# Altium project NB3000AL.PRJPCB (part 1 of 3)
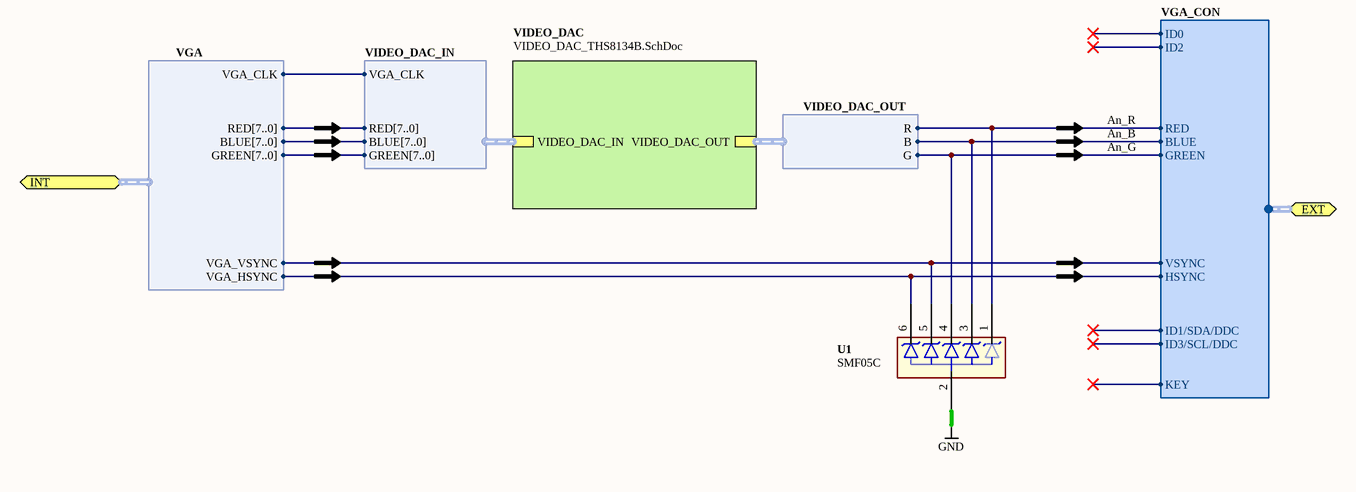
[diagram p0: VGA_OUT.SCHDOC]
ProjectAddress1: 3 Minna Close; ProjectAddress2: Belrose; ProjectAddress3: NSW 2085; ProjectAddress4: Australia; ProjectAssyNum: D-820-0053; ProjectOrganization: Altium Limited; ProjectRevision: 01; ProjectTitle: NB3000AL - Altera; ProjectTotalSheets: 106
22 sheets, 385 parts. Net scope: hierarchical (ports join the sheet entries above them; power ports are global).
Board files: NB3000AL.PcbDoc, NB3000AL_Panel.PcbDoc
Sheets:
  VGA_OUT.SCHDOC
    VIDEO_DAC = VIDEO_DAC_THS8134B.SchDoc
  Audio_Codec.SchDoc
  PSU.SchDoc
  FPGA.SCHDOC
    USER_DECOUPLING_CAPS_1V2 = FPGA_Bypass_1V2.SCHDOC
    USER_DECOUPLING_CAPS_3V3 = FPGA_Bypass_3V3.SCHDOC
    U_FPGA_Power = FPGA_NonIO.SchDoc
    PULLDOWN = PULLDNx3.SCHDOC
    PULLDOWN = PULLDNx3.SCHDOC
    PULLDOWN = PULLDNx3.SCHDOC
    PULLDOWN = PULLDNx3.SCHDOC
    PULLDOWN = PULLDNx3.SCHDOC
    PULLDOWN = PULLDNx3.SCHDOC
    PULLDOWN = PULLDNx3.SCHDOC
    PULLDOWN = PULLDNx3.SCHDOC
  LED_RGB_SMDx8.SCHDOC
  PWJACK+SWITCH.SchDoc
  Ethernet_RTL8201CL.SchDoc
  HOST_JTAG.SchDoc
  USERPWR.SchDoc
  Host_FPGA.SchDoc
    HOST_NonIO = HOST_FPGA_NonIO.SchDoc
    HOST_DECOUPLING_CAPS_1V2 = FPGA_Bypass_1V2.SCHDOC
    HOST_DECOUPLING_CAPS_3V3 = FPGA_Bypass_3V3.SCHDOC
    PULLDOWN = PULLDNx3.SCHDOC
    PULLDOWN = PULLDNx3.SCHDOC
  TSC_XPT2046.SchDoc
  USB_CY7C68001-56LFC.SchDoc
  OSC_24MHZ.SchDoc
  CON_AUDIO_AC99_NOMIC.SchDoc
  CON_FFC40_LCDTFT.SCHDOC
  Mounts.SchDoc

## Sheet VGA_OUT.SCHDOC: VGA Ouput
size A4; DocumentNumber: 2; PageSetup: Record=PageOptions|CenterHorizontal=True|CenterVertical=True|PrintScale=0.97|XCorrection=1.00|YCorrection=1.00|PrintKind=1|BorderSize=5000000|LeftOffset=0|BottomOffset=0|Orientation=2|PaperLength=1000|PaperWidth=1000|Scale=100|PaperSource=7|PrintQuality=-4|MediaType=1|DitherType=10|PaperKind=A4 (210 x 297 mm)|PrintScaleMode=1

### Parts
(Parts that share a designator on the sheet are numbered #1, #2 ... from top to bottom, then left to right.)
U1#1  SMF05C  [SC70_6L]

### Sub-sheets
VIDEO_DAC = VIDEO_DAC_THS8134B.SchDoc: VIDEO_DAC_OUT (harness VIDEO_DAC_OUT), VIDEO_DAC_IN (harness VIDEO_DAC_IN)

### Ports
EXT (harness VGA_CON), INT (harness VGA)

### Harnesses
VIDEO_DAC_IN: RED[7..0], GREEN[7..0], BLUE[7..0], VGA_CLK
VIDEO_DAC_OUT: B, R, G
VGA: RED[7..0], GREEN[7..0], BLUE[7..0], VGA_CLK, VGA_VSYNC, VGA_HSYNC
VGA_CON: RED, GREEN, BLUE, VSYNC, HSYNC, KEY, ID2, ID3/SCL/DDC, ID1/SDA/DDC, ID0

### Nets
GND: U1#1.2
An_B: U1#1.3 ; sheet VIDEO_DAC/VIDEO_DAC_OUT.B, port EXT.BLUE
An_G: U1#1.4 ; sheet VIDEO_DAC/VIDEO_DAC_OUT.G, port EXT.GREEN
An_R: U1#1.1 ; sheet VIDEO_DAC/VIDEO_DAC_OUT.R, port EXT.RED
NetU1#1_5: U1#1.5 ; port INT.VGA_VSYNC, port EXT.VSYNC
NetU1#1_6: U1#1.6 ; port INT.VGA_HSYNC, port EXT.HSYNC
NetU1#2_26: sheet VIDEO_DAC/VIDEO_DAC_IN.VGA_CLK, port INT.VGA_CLK

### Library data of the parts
U1#1 = D-157-0000: TVS Diode Array  For ESD and Latch-Up Protection; Junction Capacitance: 130 pF; Peak Pulse Current: 8 A; Peak Pulse Power: 100 W; Reverse Breakdown Voltage: 6 V

## Sheet VIDEO_DAC_THS8134B.SchDoc: Video DAC
size A4; Organization: Altium Limited.; Address1: Level 3, 12a Rodborough Rd; Address2: Frenchs Forest 2086; Address3: NSW; Address4: AUSTRALIA; DocumentNumber: 62; SheetNumber: 63; SheetTotal: 78
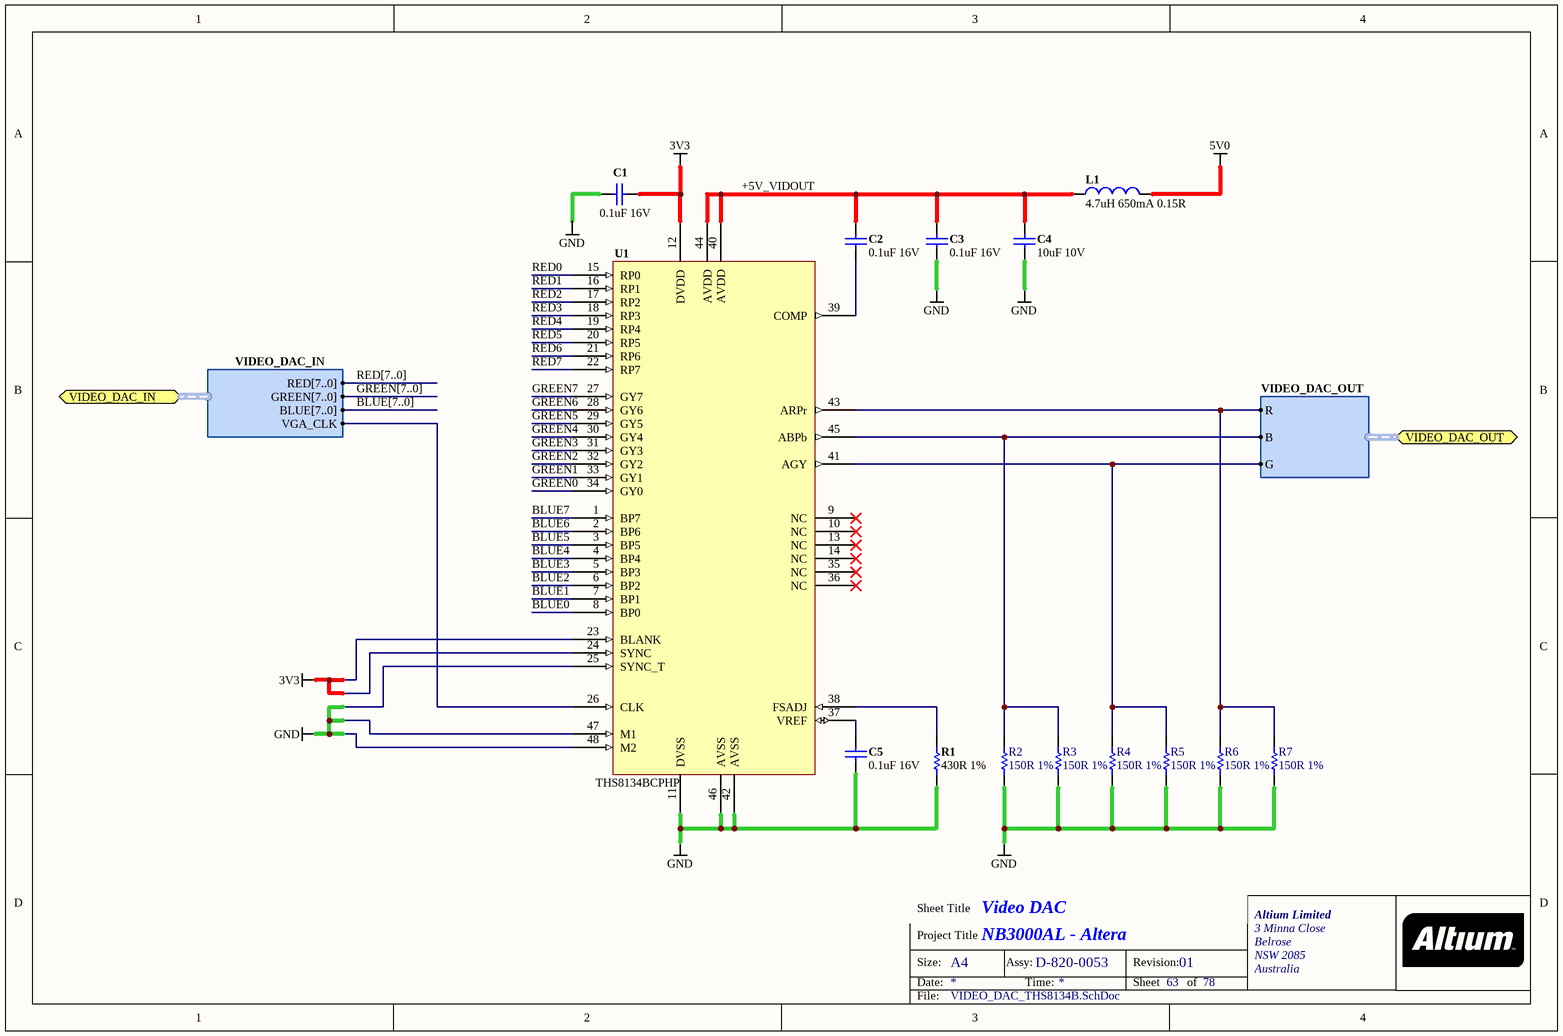
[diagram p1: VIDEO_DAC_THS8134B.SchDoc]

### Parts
(Parts that share a designator on the sheet are numbered #1, #2 ... from top to bottom, then left to right.)
C1#1  0.1uF 16V  [CAPC1005-STAR]
C2#1  0.1uF 16V  [CAPC1005-STAR]
C3#1  0.1uF 16V  [CAPC1005-STAR]
C4#1  10uF 10V  [CAPC2012-STAR]
C5#1  0.1uF 16V  [CAPC1005-STAR]
L1#1  4.7uH 650mA 0.15R  [INDC3225]
R1#1  430R 1%  [RESC1005-STAR]
R2#1  150R 1%  [RESC1005-STAR]
R3#1  150R 1%  [RESC1005-STAR]
R4#1  150R 1%  [RESC1005-STAR]
R5#1  150R 1%  [RESC1005-STAR]
R6#1  150R 1%  [RESC1005-STAR]
R7#1  150R 1%  [RESC1005-STAR]
U1#2  THS8134BCPHP  [TSQFP50P900X900_HS-48]

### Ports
VIDEO_DAC_IN (harness VIDEO_DAC_IN), VIDEO_DAC_OUT (harness VIDEO_DAC_OUT)

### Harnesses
VIDEO_DAC_OUT: B, R, G
VIDEO_DAC_IN: RED[7..0], GREEN[7..0], BLUE[7..0], VGA_CLK

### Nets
3V3: C1#1.1 U1#2.12(DVDD) U1#2.23(BLANK) U1#2.24(SYNC)
5V0: L1#1.1
GND: C1#1.2 C3#1.2 C4#1.1 C5#1.2 R1#1.1 R2#1.2 R3#1.1 R4#1.2 R5#1.1 R6#1.1 R7#1.1 U1#2.11(DVSS) U1#2.25(SYNC_T) U1#2.42(AVSS) U1#2.46(AVSS) U1#2.47(M1) U1#2.48(M2)
+5V_VIDOUT: C2#1.1 C3#1.1 C4#1.2 L1#1.2 U1#2.40(AVDD) U1#2.44(AVDD)
An_B: R2#1.1 R3#1.2 U1#2.45(ABPb) ; port VIDEO_DAC_OUT.B
An_G: R4#1.1 R5#1.2 U1#2.41(AGY) ; port VIDEO_DAC_OUT.G
An_R: R6#1.2 R7#1.2 U1#2.43(ARPr) ; port VIDEO_DAC_OUT.R
BLUE0: U1#2.8(BP0)
BLUE1: U1#2.7(BP1)
BLUE2: U1#2.6(BP2)
BLUE3: U1#2.5(BP3)
BLUE4: U1#2.4(BP4)
BLUE5: U1#2.3(BP5)
BLUE6: U1#2.2(BP6)
BLUE7: U1#2.1(BP7)
GREEN0: U1#2.34(GY0)
GREEN1: U1#2.33(GY1)
GREEN2: U1#2.32(GY2)
GREEN3: U1#2.31(GY3)
GREEN4: U1#2.30(GY4)
GREEN5: U1#2.29(GY5)
GREEN6: U1#2.28(GY6)
GREEN7: U1#2.27(GY7)
RED0: U1#2.15(RP0)
RED1: U1#2.16(RP1)
RED2: U1#2.17(RP2)
RED3: U1#2.18(RP3)
RED4: U1#2.19(RP4)
RED5: U1#2.20(RP5)
RED6: U1#2.21(RP6)
RED7: U1#2.22(RP7)
NetC2#1_2: C2#1.2 U1#2.39(COMP)
NetC5#1_1: C5#1.1 U1#2.37(VREF)
NetR1#1_2: R1#1.2 U1#2.38(FSADJ)
NetU1#2_26: U1#2.26(CLK) ; port VIDEO_DAC_IN.VGA_CLK

Not connected (* = marked no-connect by the designer): U1#2 9(NC)* 10(NC)* 13(NC)* 14(NC)* 35(NC)* 36(NC)*

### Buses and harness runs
bus BLUE[7..0]
bus GREEN[7..0]
bus RED[7..0]

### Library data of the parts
C1#1 C2#1 C3#1 C5#1 = D-101-0080: Capacitor, Ceramic, 0.1uF 10% 16V 0402 (1005) X7R; Polarity: Non-Polarized
C4#1 = D-101-0087: Capacitor, Ceramic, 10uF 10% 10V 0805 (2012) X5R; Polarity: Non-Polarized
L1#1 = D-102-0005: Inductor, 4.7uH 650mA 0.15R 1210 (3225) LQH32CN4R7M11L
R1#1 = D-100-0096: Resistor, 430R 1% 0402 (1005); Power Rating: 63 mW
R2#1 R3#1 R4#1 R5#1 R6#1 R7#1 = D-100-0005: Resistor, 150R 1% 0402 (1005); Power Rating: 63mW
U1#2 = D-222-0000: THS8134BCPHP, Triple 8-Bit, 80 MSPS Video DAC with Tri-Level Sync Generation

## Sheet Audio_Codec.SchDoc: Audio CODEC Top
size A4; DocumentNumber: 4
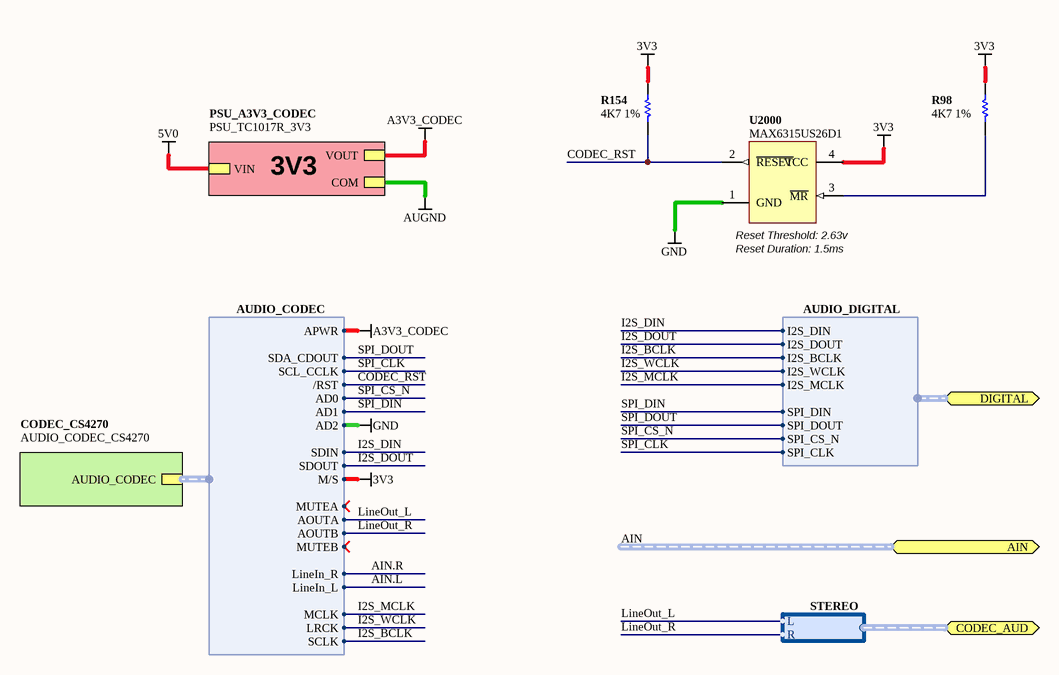
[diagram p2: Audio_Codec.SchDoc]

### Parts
(Parts that share a designator on the sheet are numbered #1, #2 ... from top to bottom, then left to right.)
R98  4K7 1%  [RESC1005-STAR]
R154#1  4K7 1%  [RESC1005-STAR]
U2000  MAX6315US26D1  [SOT143]

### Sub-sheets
CODEC_CS4270 = AUDIO_CODEC_CS4270 (file not in this document): AUDIO_CODEC (harness AUDIO_CODEC)
PSU_A3V3_CODEC = PSU_TC1017R_3V3 (file not in this document): VIN, VOUT, COM

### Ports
AIN (harness AUDIO_IN), CODEC_AUD (harness STEREO), DIGITAL (harness AUDIO_DIGITAL)

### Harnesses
AUDIO_CODEC: SDOUT, SDIN, SCLK, LRCK, MCLK, M/S, LineIn_L, LineIn_R, AOUTA, AOUTB, APWR, SCL_CCLK, AD1, SDA_CDOUT, AD0, AD2, /RST, MUTEA, MUTEB
AUDIO_DIGITAL: I2S_DOUT, I2S_DIN, I2S_BCLK, I2S_WCLK, I2S_MCLK, SPI_CLK, SPI_DIN, SPI_DOUT, SPI_CS_N
STEREO: L, R

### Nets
3V3: R98.2 R154#1.2 U2000.4(VCC) ; sheet CODEC_CS4270/AUDIO_CODEC.M/S
A3V3_CODEC: sheet PSU_A3V3_CODEC/VOUT, sheet CODEC_CS4270/AUDIO_CODEC.APWR
GND: U2000.1(GND) ; sheet CODEC_CS4270/AUDIO_CODEC.AD2
CODEC_RST: R154#1.1 U2000.2(~{RESET}) ; sheet CODEC_CS4270/AUDIO_CODEC./RST
I2S_BCLK: sheet CODEC_CS4270/AUDIO_CODEC.SCLK, port DIGITAL.I2S_BCLK
I2S_DIN: sheet CODEC_CS4270/AUDIO_CODEC.SDIN, port DIGITAL.I2S_DIN
I2S_DOUT: sheet CODEC_CS4270/AUDIO_CODEC.SDOUT, port DIGITAL.I2S_DOUT
I2S_MCLK: sheet CODEC_CS4270/AUDIO_CODEC.MCLK, port DIGITAL.I2S_MCLK
I2S_WCLK: sheet CODEC_CS4270/AUDIO_CODEC.LRCK, port DIGITAL.I2S_WCLK
LineOut_L: sheet CODEC_CS4270/AUDIO_CODEC.AOUTA, port CODEC_AUD.L
LineOut_R: sheet CODEC_CS4270/AUDIO_CODEC.AOUTB, port CODEC_AUD.R
SPI_CLK: sheet CODEC_CS4270/AUDIO_CODEC.SCL_CCLK, port DIGITAL.SPI_CLK
SPI_CS_N: sheet CODEC_CS4270/AUDIO_CODEC.AD0, port DIGITAL.SPI_CS_N
SPI_DIN: sheet CODEC_CS4270/AUDIO_CODEC.AD1, port DIGITAL.SPI_DIN
SPI_DOUT: sheet CODEC_CS4270/AUDIO_CODEC.SDA_CDOUT, port DIGITAL.SPI_DOUT
NetR98_1: R98.1 U2000.3(~{MR})

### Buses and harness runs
harness AIN = port AIN

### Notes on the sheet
- 3V3
- (near U2000) Reset Threshold: 2.63v
- (near U2000) Reset Duration: 1.5ms

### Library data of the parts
R98 R154#1 = D-100-0088: Resistor, 4K7 1% 0402 (1005); Power Rating: 63 mW; Resistance: 4.7 K
U2000 = D-243-0000: MAX6315, Open-Drain Output SOT Reset IC, Customized Reset Thresholds, Timeout Delays

## Sheet PSU.SchDoc: NB3000 POWER SUPPLIES
size A4; Organization: Altium Limited.; DocumentNumber: 7; Revision: 6
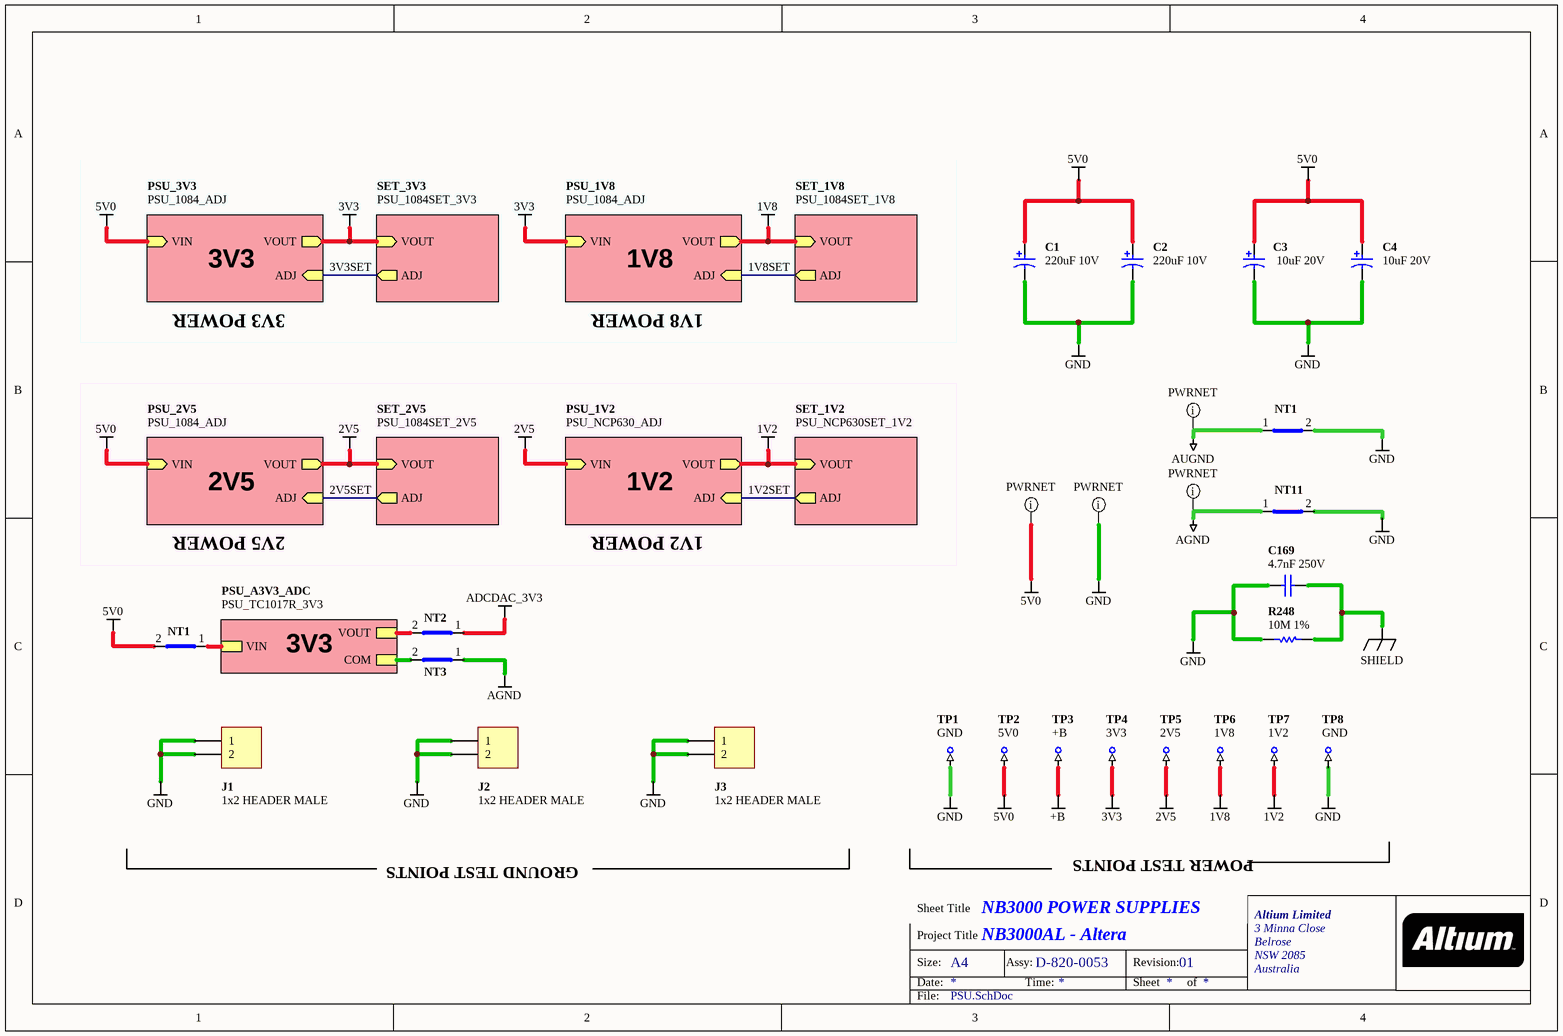
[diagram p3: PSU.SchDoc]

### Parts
(Parts that share a designator on the sheet are numbered #1, #2 ... from top to bottom, then left to right.)
C1#2  220uF 10V  [CAPC7343-STAR]
C2#2  220uF 10V  [CAPC7343-STAR]
C3#2  10uF 20V  [CAPC3528-STAR]
C4#2  10uF 20V  [CAPC3528-STAR]
C169  4.7nF 250V  [CAPM7163]
J1#1  1x2 HEADER MALE  [HDR1X2]
J2  1x2 HEADER MALE  [HDR1X2]
J3#1  1x2 HEADER MALE  [HDR1X2]
NT1#1  Net Tie SMT2  [NETTIE-SMT2-31X39]  (value not drawn)  (net tie, no BOM)
NT1#2  Net Tie SMT2  [NETTIE-SMT2-31X51]  (value not drawn)  (net tie, no BOM)
NT2#1  Net Tie SMT2  [NETTIE-SMT2-31X51]  (value not drawn)  (net tie, no BOM)
NT3#1  Net Tie SMT2  [NETTIE-SMT2-31X51]  (value not drawn)  (net tie, no BOM)
NT11#1  Net Tie SMT2  [NETTIE-SMT2-8X8]  (value not drawn)  (net tie, no BOM)
R248  10M 1%  [RESC3216]
TP1  GND  [TestPin]  (no BOM)
TP2  5V0  [TestPin]  (no BOM)
TP3  +B  [TestPin]  (no BOM)
TP4  3V3  [TestPin]  (no BOM)
TP5  2V5  [TestPin]  (no BOM)
TP6  1V8  [TestPin]  (no BOM)
TP7  1V2  [TestPin]  (no BOM)
TP8  GND  [TestPin]  (no BOM)

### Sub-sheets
PSU_1V2 = PSU_NCP630_ADJ (file not in this document): VIN (in), VOUT (out), ADJ (in)
PSU_1V8 = PSU_1084_ADJ (file not in this document): VIN (in), VOUT (out), ADJ (in)
PSU_2V5 = PSU_1084_ADJ (file not in this document): VIN (in), VOUT (out), ADJ (in)
PSU_3V3 = PSU_1084_ADJ (file not in this document): VIN (in), VOUT (out), ADJ (in)
PSU_A3V3_ADC = PSU_TC1017R_3V3 (file not in this document): VIN, VOUT, COM
SET_1V2 = PSU_NCP630SET_1V2 (file not in this document): VOUT (in), ADJ (out)
SET_1V8 = PSU_1084SET_1V8 (file not in this document): VOUT (in), ADJ (out)
SET_2V5 = PSU_1084SET_2V5 (file not in this document): VOUT (in), ADJ (out)
SET_3V3 = PSU_1084SET_3V3 (file not in this document): VOUT (in), ADJ (out)

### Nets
1V2: TP7.1 ; sheet PSU_1V2/VOUT, sheet SET_1V2/VOUT
1V8: TP6.1 ; sheet PSU_1V8/VOUT, sheet SET_1V8/VOUT
2V5: TP5.1 ; sheet PSU_1V2/VIN, sheet PSU_2V5/VOUT, sheet SET_2V5/VOUT
3V3: TP4.1 ; sheet PSU_1V8/VIN, sheet PSU_3V3/VOUT, sheet SET_3V3/VOUT
5V0: C1#2.1 C2#2.1 C3#2.1 C4#2.1 NT1#2.2(Net2) TP2.1 ; sheet PSU_2V5/VIN, sheet PSU_3V3/VIN
+B: TP3.1
ADCDAC_3V3: NT2#1.1(Net1)
AGND: NT3#1.1(Net1) NT11#1.1(Net1)
AUGND: NT1#1.1(Net1)
GND: C1#2.2 C2#2.2 C3#2.2 C4#2.2 C169.2 J1#1.1 J1#1.2 J2.1 J2.2 J3#1.1 J3#1.2 NT1#1.2(Net2) NT11#1.2(Net2) R248.2 TP1.1 TP8.1
SHIELD: C169.1 R248.1
1V2SET: sheet PSU_1V2/ADJ, sheet SET_1V2/ADJ
1V8SET: sheet PSU_1V8/ADJ, sheet SET_1V8/ADJ
2V5SET: sheet PSU_2V5/ADJ, sheet SET_2V5/ADJ
3V3SET: sheet PSU_3V3/ADJ, sheet SET_3V3/ADJ
NetNT1#2_1: NT1#2.1(Net1) ; sheet PSU_A3V3_ADC/VIN
NetNT2#1_2: NT2#1.2(Net2) ; sheet PSU_A3V3_ADC/VOUT
NetNT3#1_2: NT3#1.2(Net2) ; sheet PSU_A3V3_ADC/COM

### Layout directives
net class PWRNET: 5V0, AGND, AUGND, GND

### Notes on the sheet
- 3V3
- 3V3 POWER
- 1V8
- 1V8 POWER
- 2V5
- 1V2
- 2V5 POWER
- 1V2 POWER
- POWER TEST POINTS
- GROUND TEST POINTS

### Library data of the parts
C1#2 C2#2 = D-101-0088: Capacitor, Tantalum, 220uF 10% 10V MCCT-D (7343-31); Polarity: Polarized
C3#2 C4#2 = D-101-0007: Capacitor, Tantalum, 10uF 10% 20V MCCT-B (3528); Polarity: Polarized
C169 = D-101-0019: Capacitor, Ceramic, 4.7nF 20% 250V Panasonic BC J Lead (CAPM7163) Y5V; Polarity: Non-Polarized; Tolerance: 20% %
J1#1 J2 J3#1 = D-300-0020: Header IDC, 2 x 1 Pin Vertical 2.54mm Pitch (Non-Boxed, Male); Max Current: 3 A
NT1#1 NT11#1 = D-002-0004: Net-Tie, Surface Mount, 2 x 2.0mm x 0.8mm SMT Pads - For 0.8mm Track
NT1#2 NT2#1 NT3#1 = D-002-0003: Net-Tie, Surface Mount, 2 x 1.6mm x 0.8mm SMT Pads - For 0.8mm Track
R248 = D-100-0059: Resistor, 10M 1%1206 (3216); Power Rating: 250 mW
TP1-TP8 = D-006-0000: Test Point, PCB Mount with Silkscreen Box

## Sheet FPGA.SCHDOC: USER FPGA Connections
size A0; Organization: Altium Limited.; PageSetup: Record=PageOptions|CenterHorizontal=True|CenterVertical=True|PrintScale=0.50|XCorrection=1.00|YCorrection=1.00|PrintKind=0|BorderSize=5000000|LeftOffset=0|BottomOffset=0|Orientation=2|PaperLength=4199|PaperWidth=2969|Scale=100|PaperSource=7|PrintQuality=600|MediaType=1|DitherType=10|PaperKind=A3 (297 x 420 mm)|PrintScaleMode=1
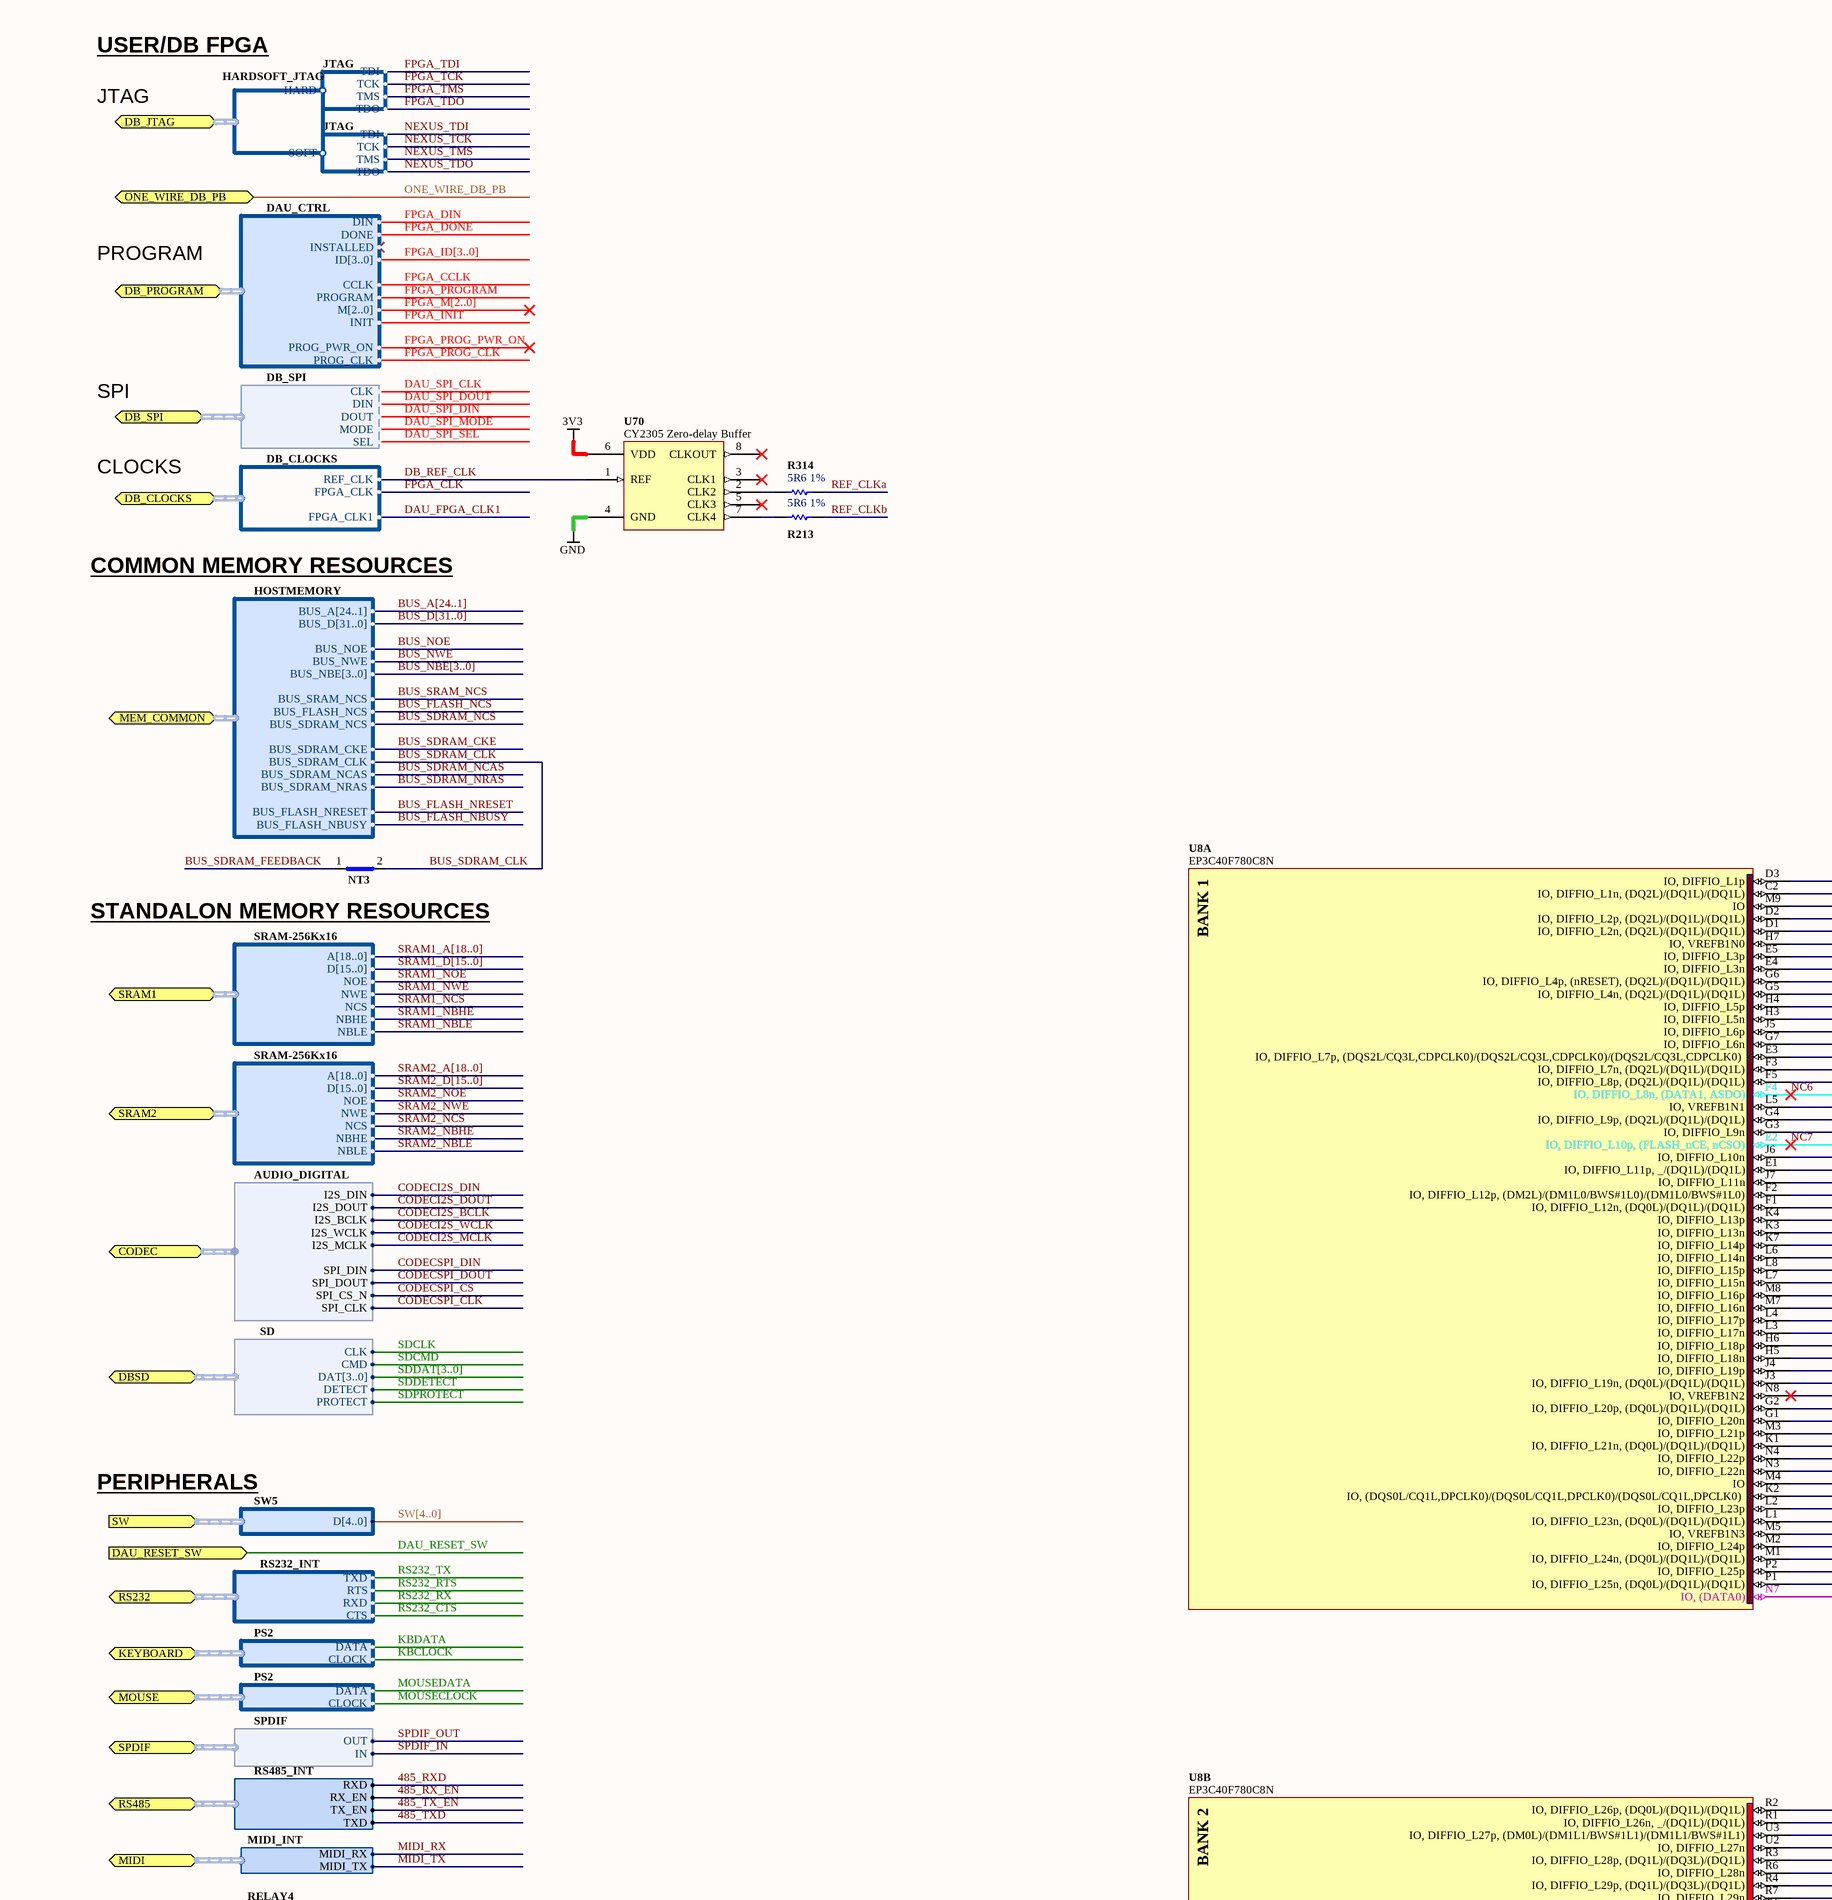
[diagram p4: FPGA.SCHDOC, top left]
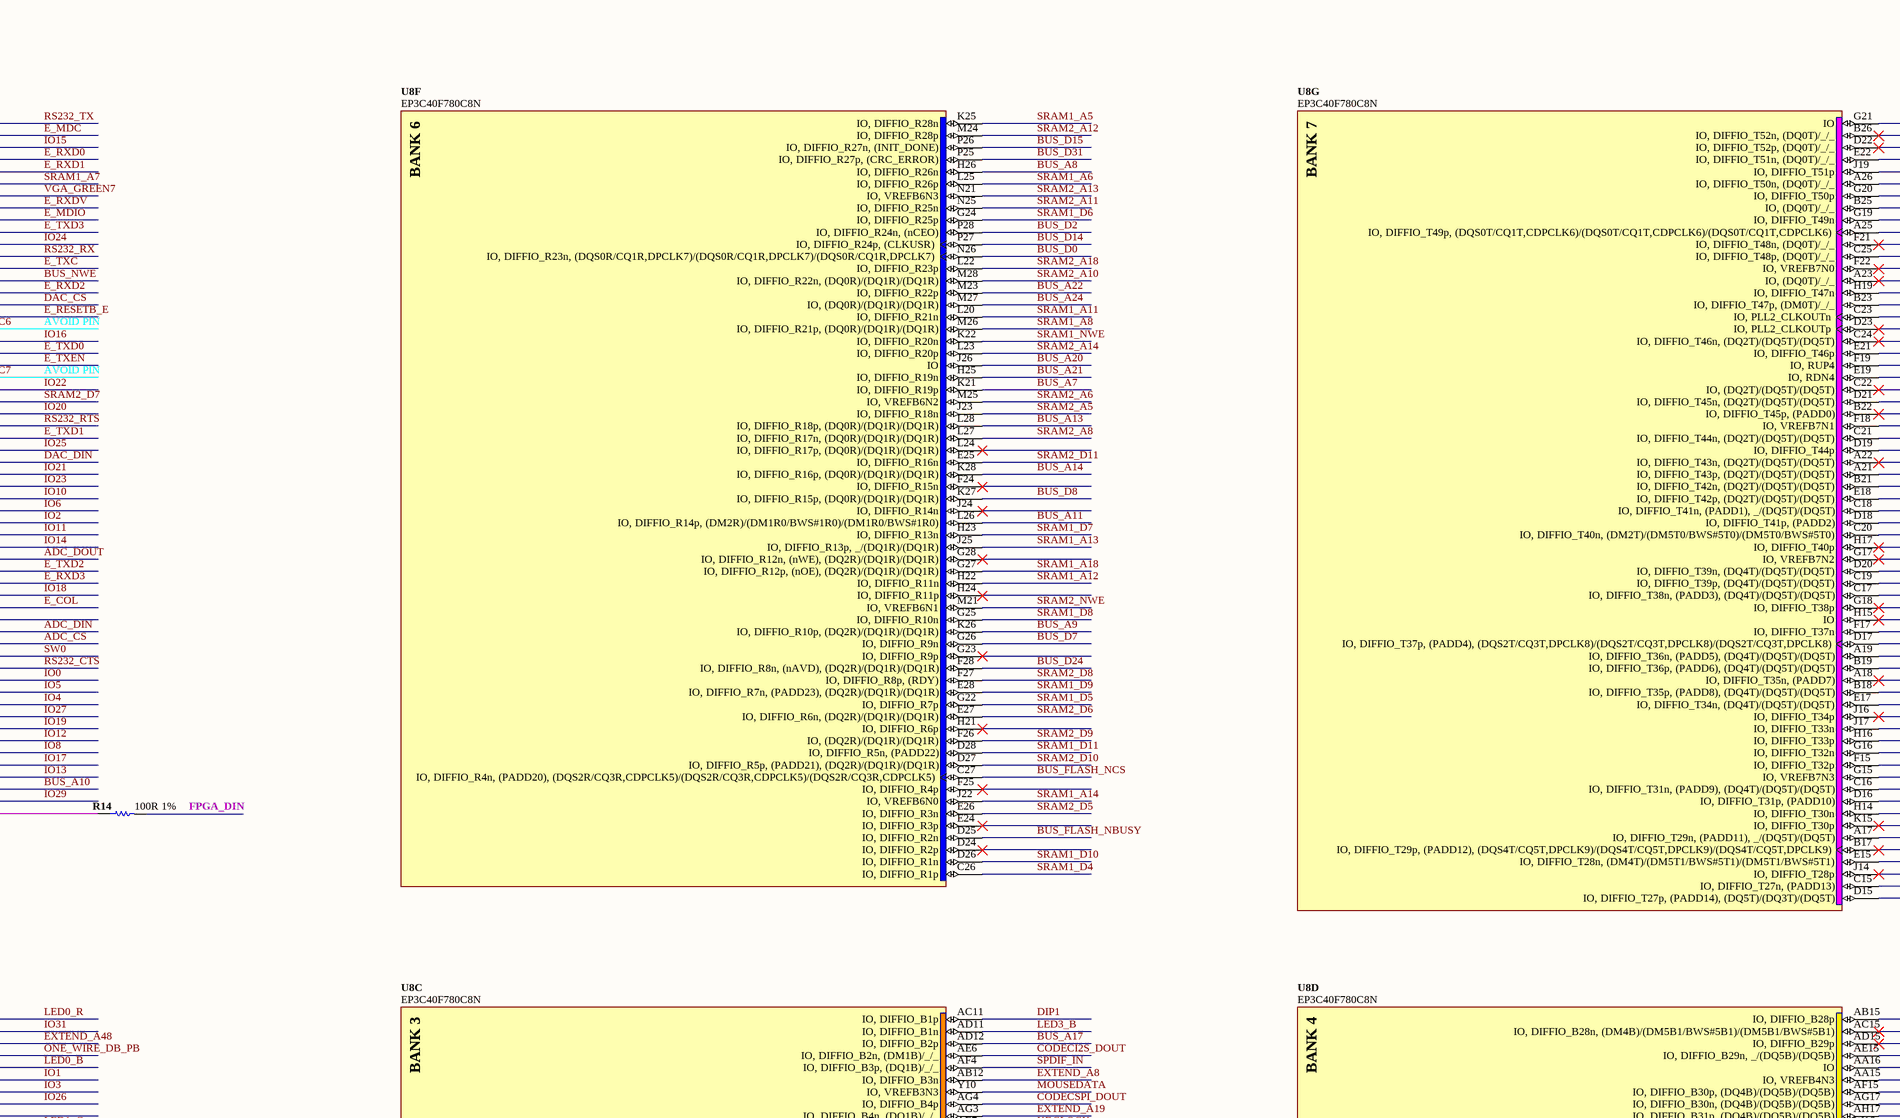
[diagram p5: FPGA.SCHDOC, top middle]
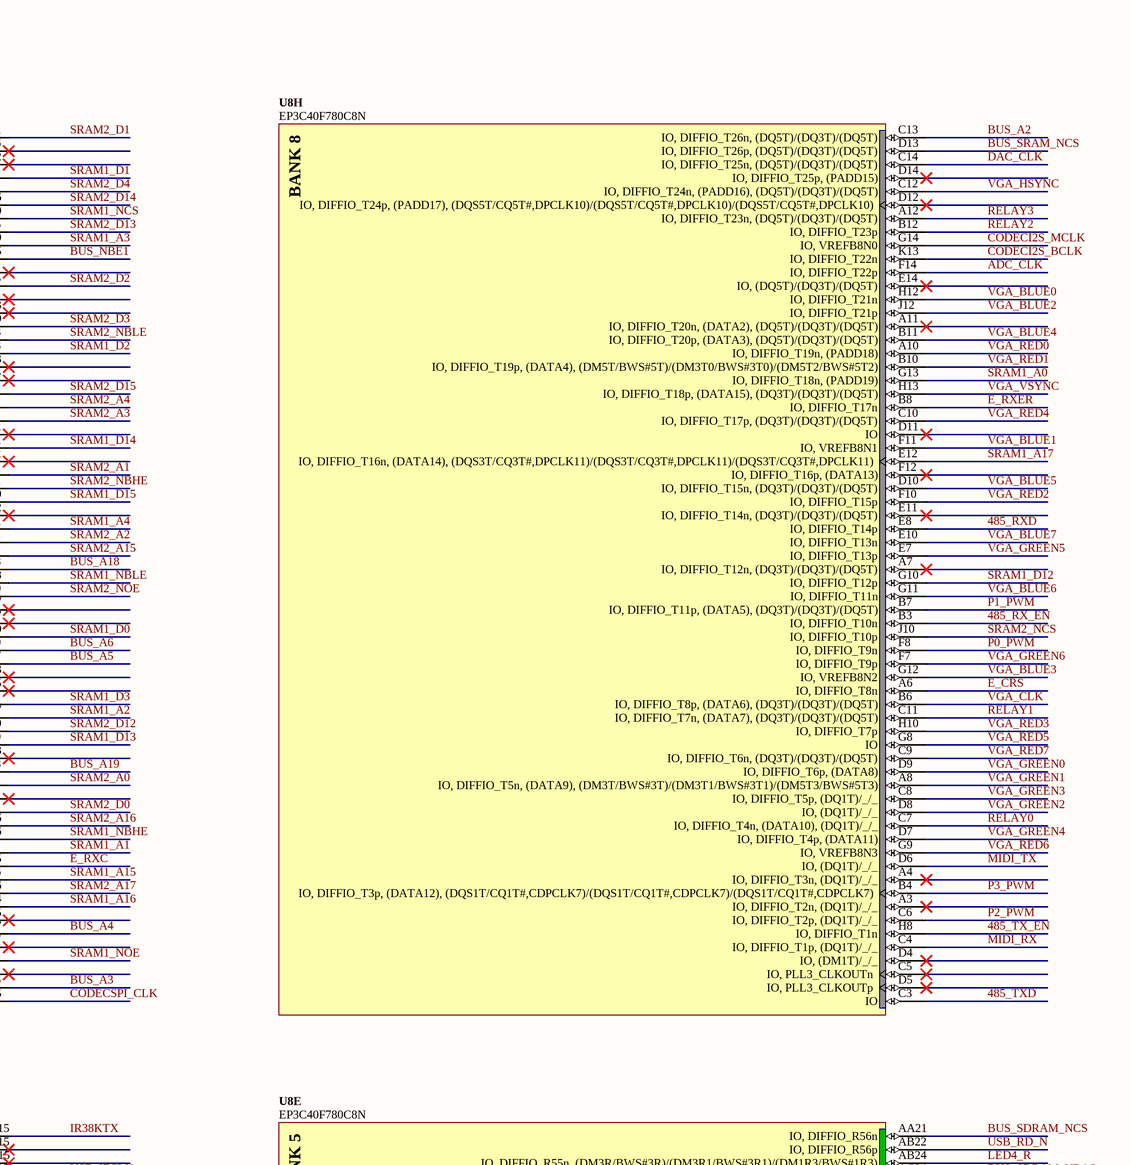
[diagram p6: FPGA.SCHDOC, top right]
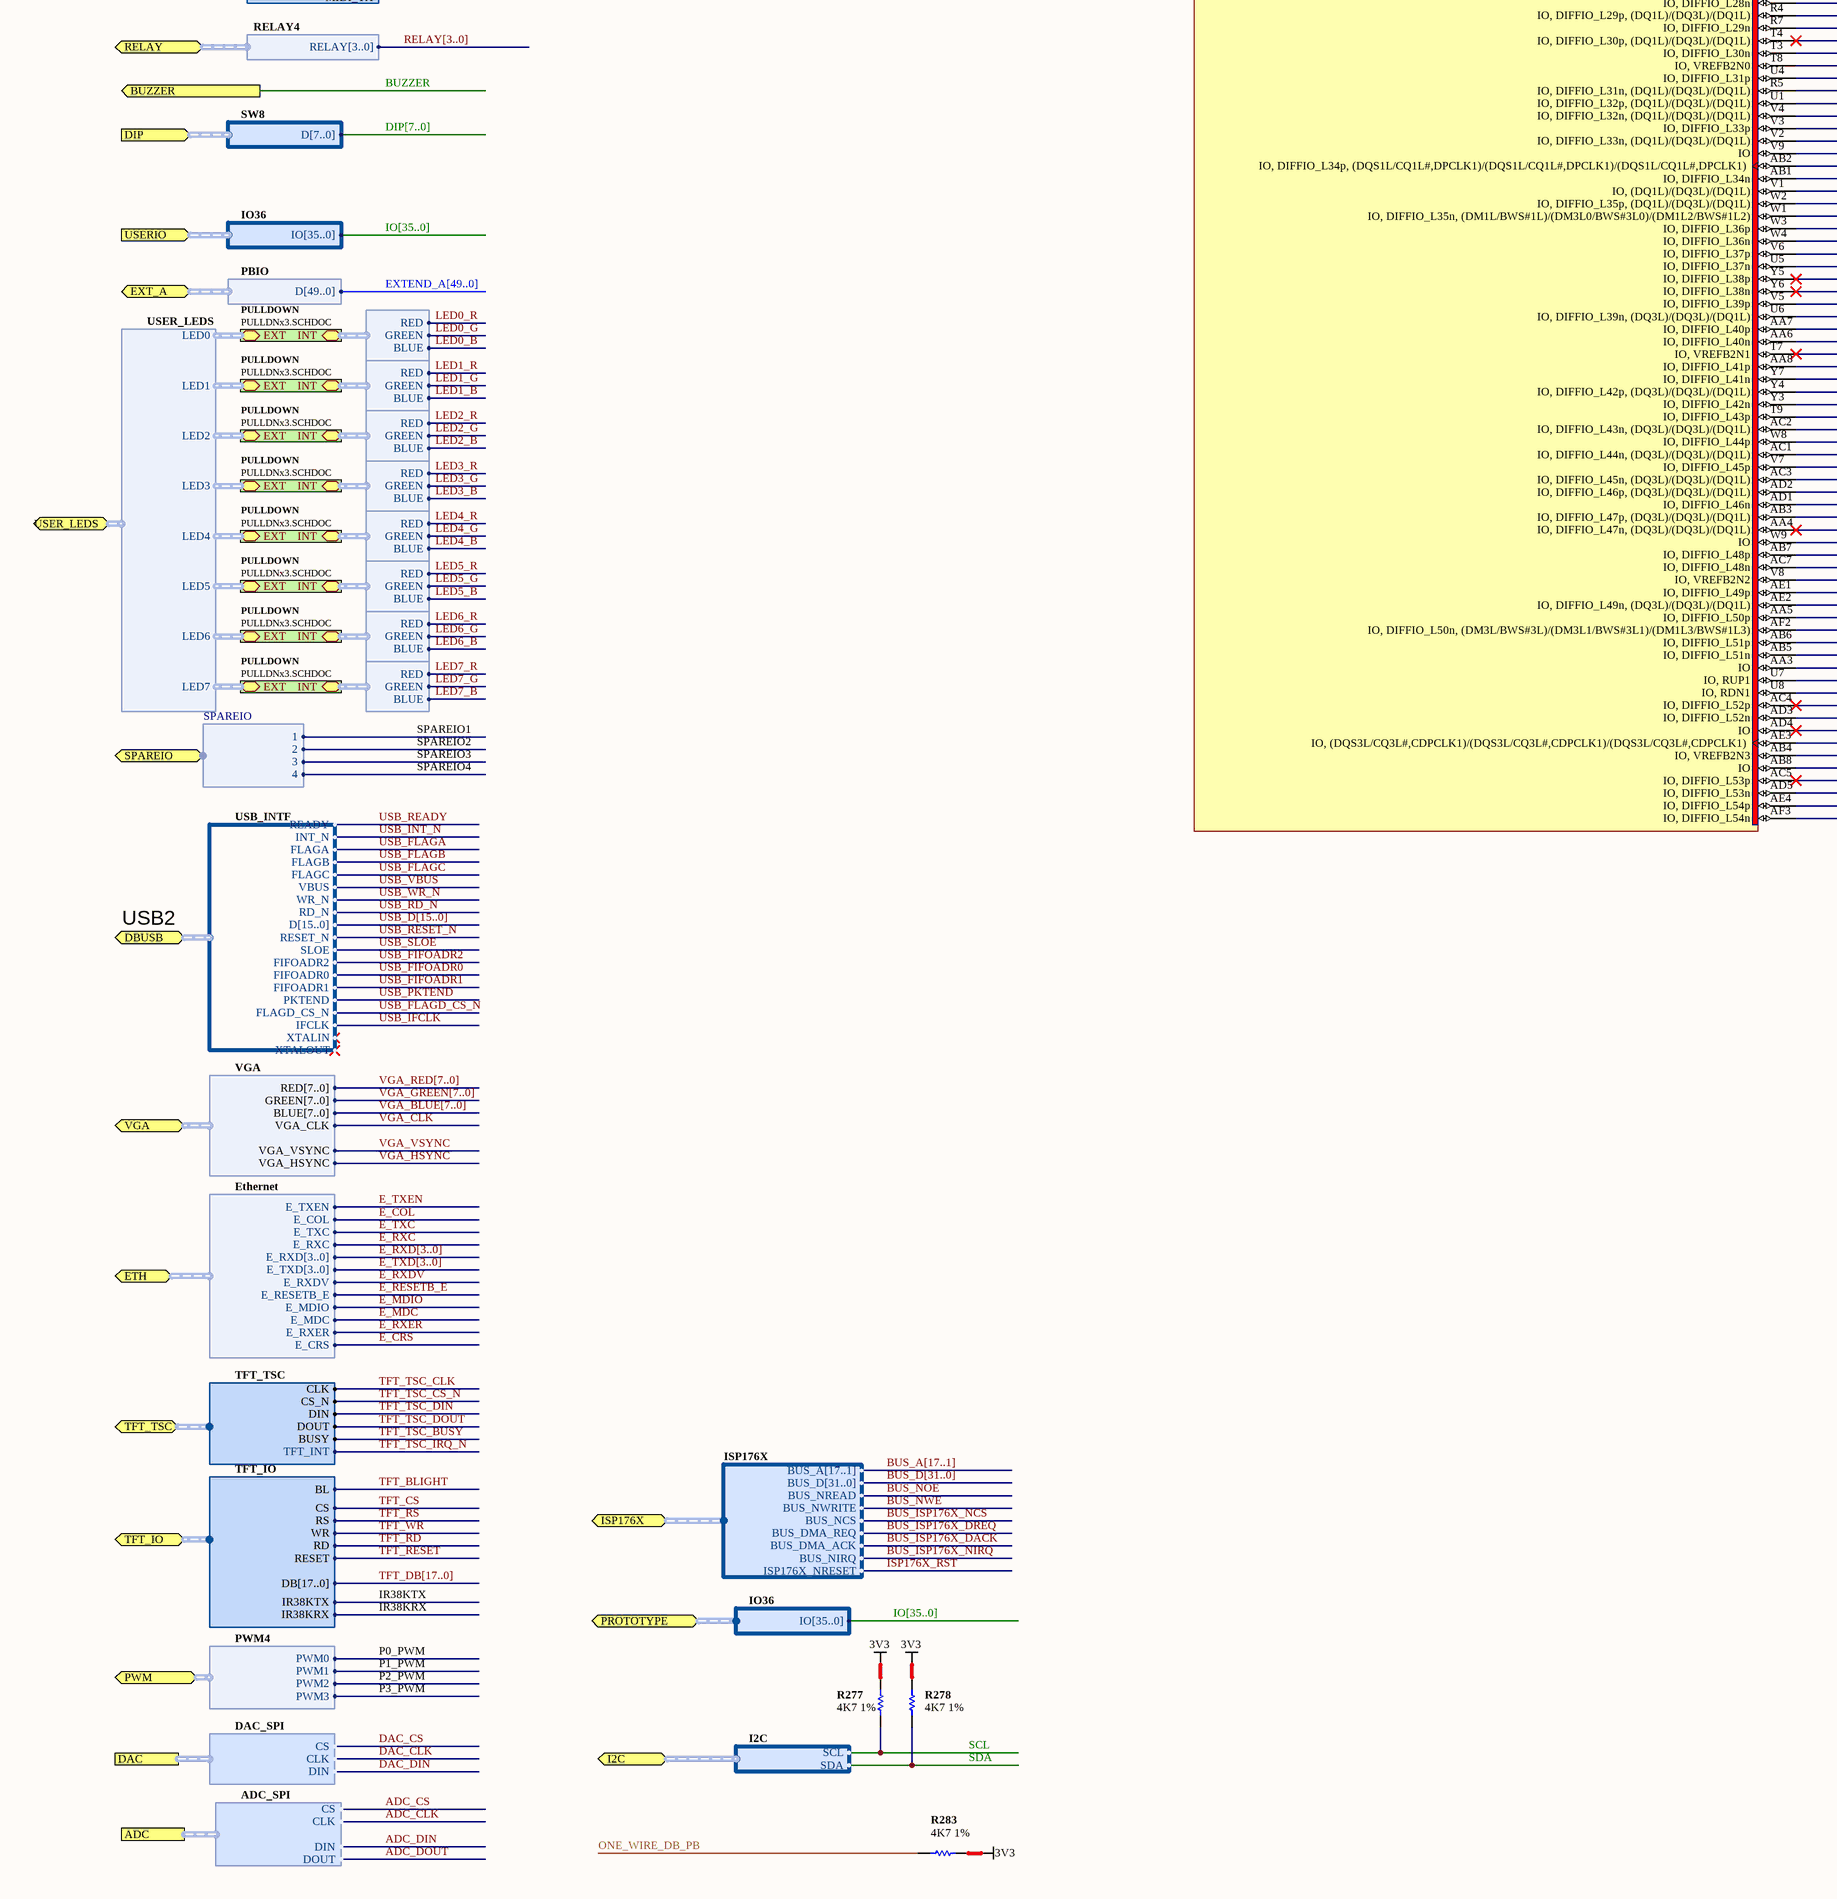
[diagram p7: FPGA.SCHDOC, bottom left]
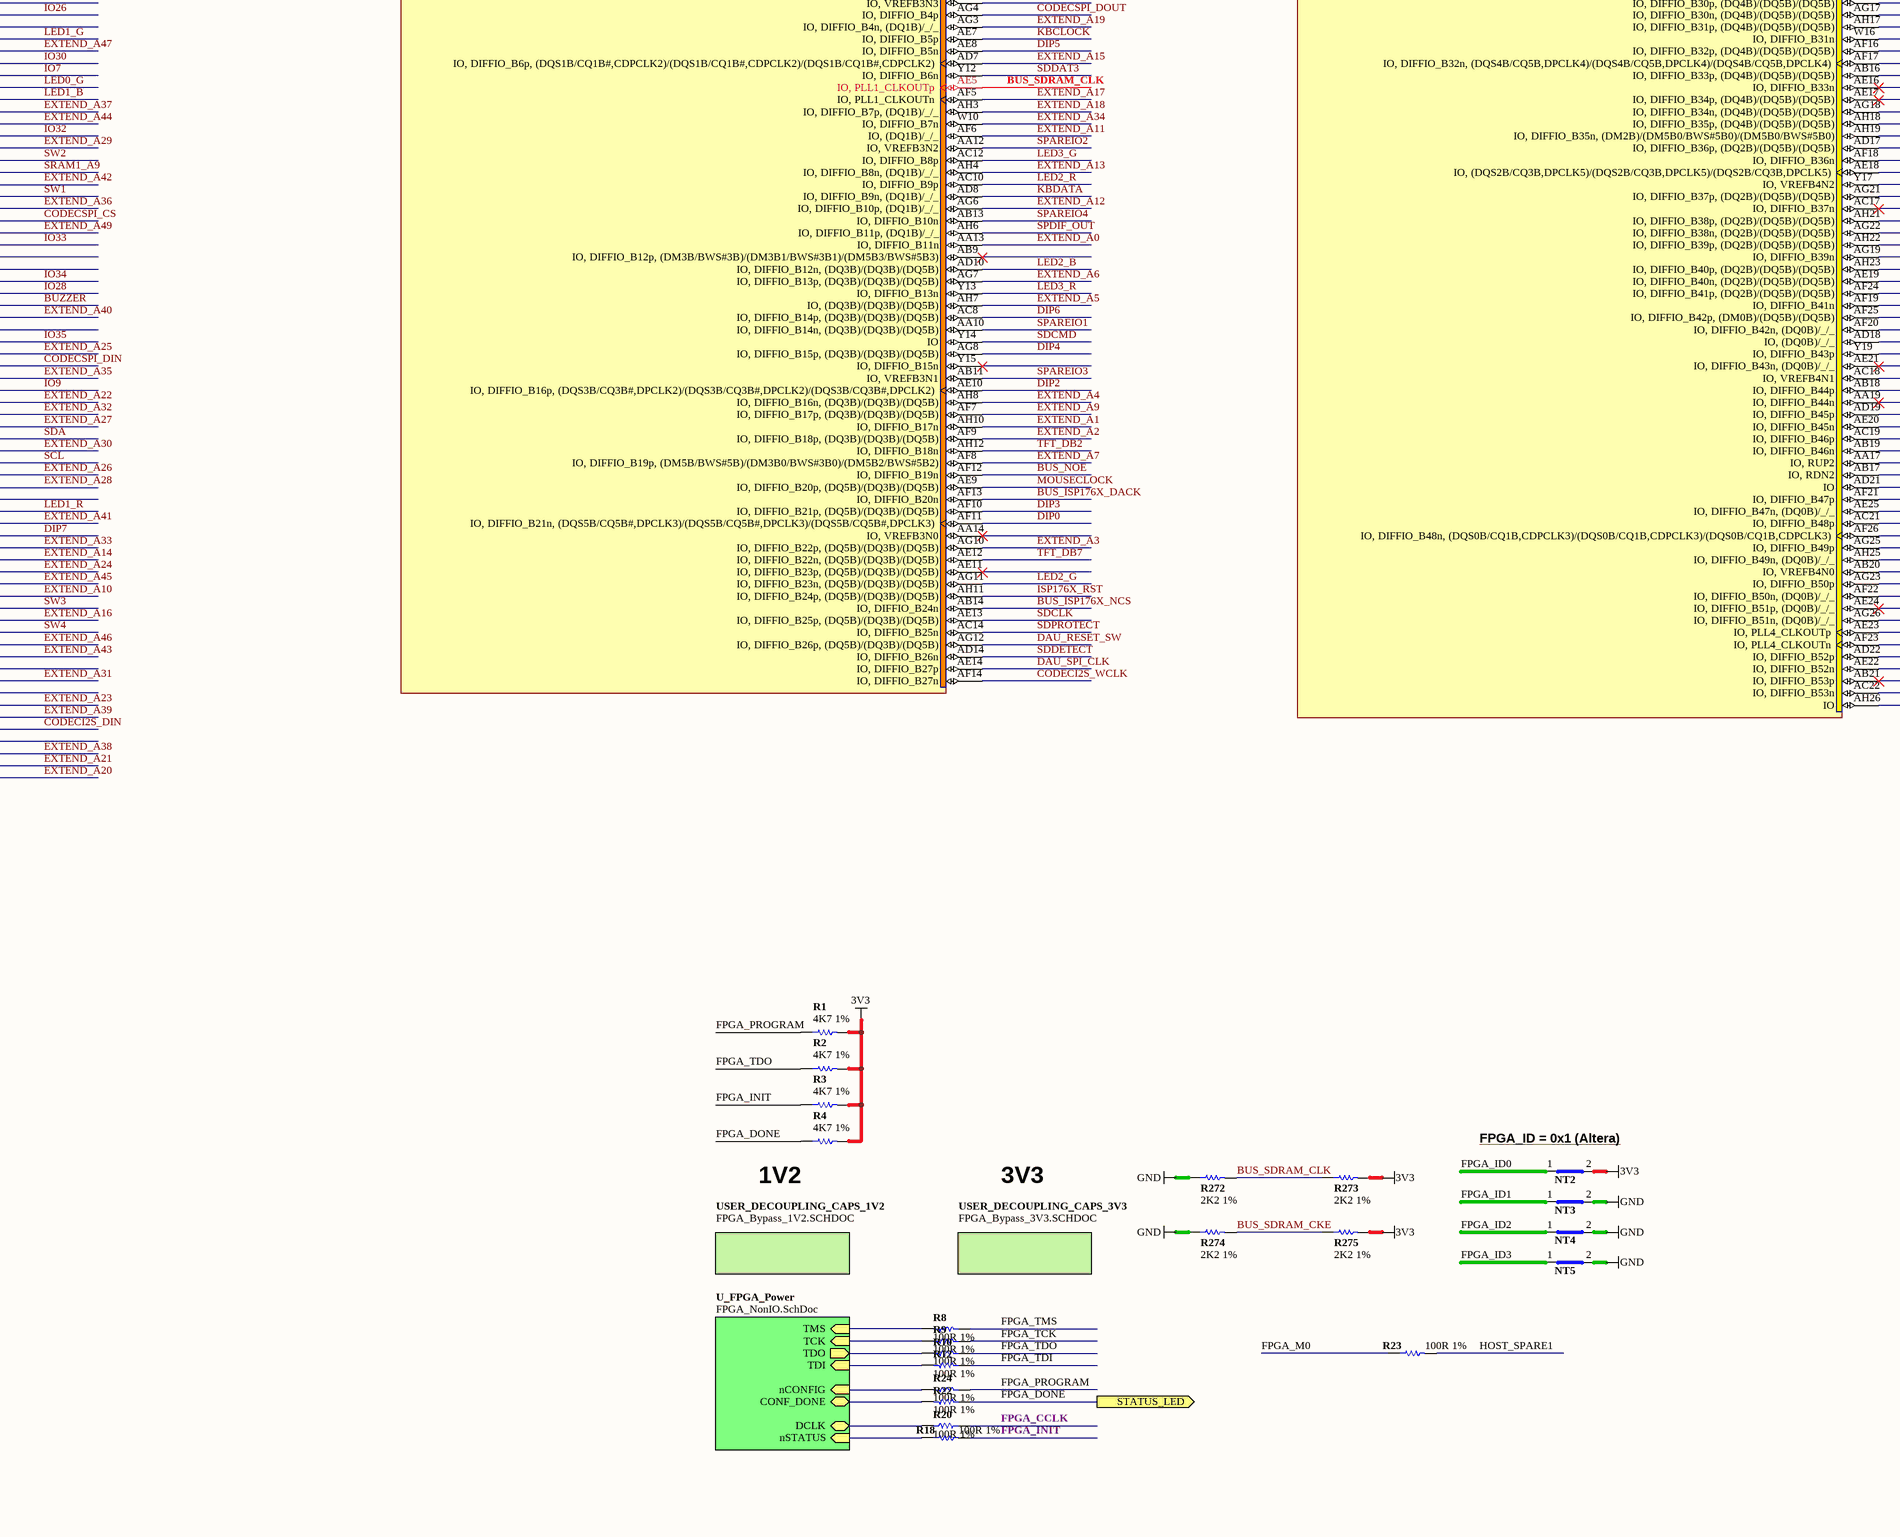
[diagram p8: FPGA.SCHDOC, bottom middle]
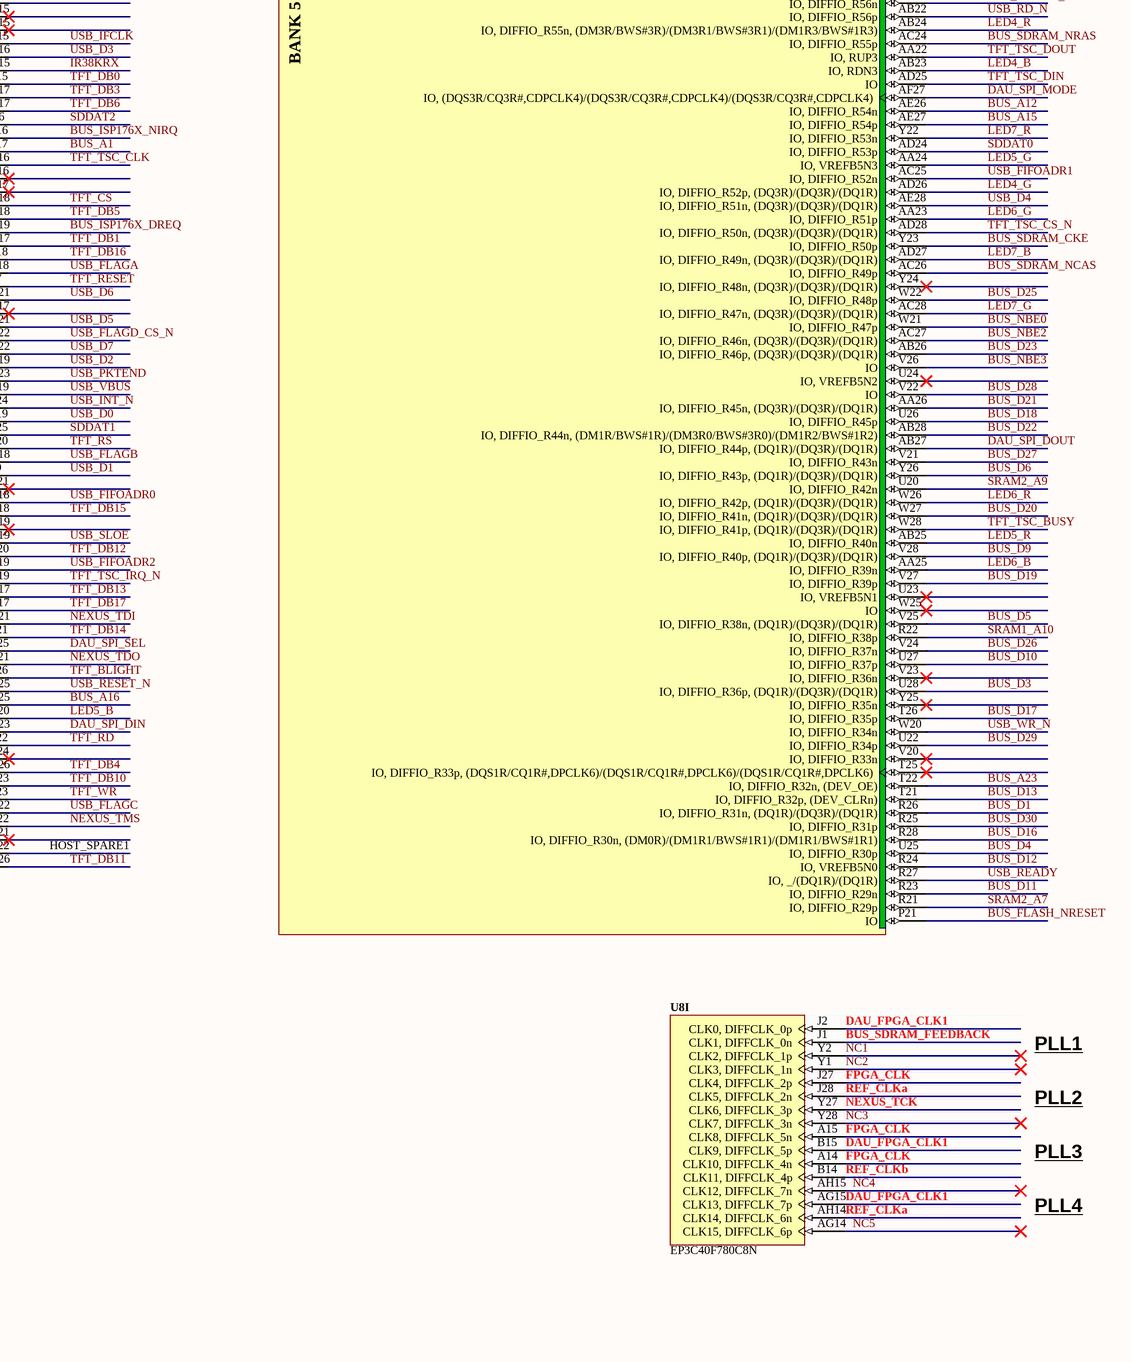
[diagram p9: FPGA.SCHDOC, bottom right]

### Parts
(Parts that share a designator on the sheet are numbered #1, #2 ... from top to bottom, then left to right.)
NT2#2  Net Tie SMT2  [NETTIE-SMT2-8X8]  (value not drawn)  (net tie, no BOM)
NT3#2  Net Tie SMT2  [NETTIE-SMT2-8X8]  (value not drawn)  (net tie, no BOM)
NT3#3  Net Tie SMT2  [NETTIE-SMT2-8X8]  (value not drawn)  (net tie, no BOM)
NT4  Net Tie SMT2  [NETTIE-SMT2-8X8]  (value not drawn)  (net tie, no BOM)
NT5  Net Tie SMT2  [NETTIE-SMT2-8X8]  (value not drawn)  (net tie, no BOM)
R1#2  4K7 1%  [RESC1005-STAR]
R2#2  4K7 1%  [RESC1005-STAR]
R3#2  4K7 1%  [RESC1005-STAR]
R4#2  4K7 1%  [RESC1005-STAR]
R8#1  100R 1%  [RESC1005-STAR]
R9#1  100R 1%  [RESC1005-STAR]
R10#1  100R 1%  [RESC1005-STAR]
R12#1  100R 1%  [RESC1005-STAR]
R14#1  100R 1%  [RESC1005-STAR]
R18#1  100R 1%  [RESC1005-STAR]
R20#1  100R 1%  [RESC1005-STAR]
R22#1  100R 1%  [RESC1005-STAR]
R23#1  100R 1%  [RESC1005-STAR]
R24#1  100R 1%  [RESC1005-STAR]
R213  5R6 1%  [RESC1005-STAR]
R272  2K2 1%  [RESC1005-STAR]
R273  2K2 1%  [RESC1005-STAR]
R274  2K2 1%  [RESC1005-STAR]
R275  2K2 1%  [RESC1005-STAR]
R277  4K7 1%  [RESC1005-STAR]
R278  4K7 1%  [RESC1005-STAR]
R283  4K7 1%  [RESC1005-STAR]
R314  5R6 1%  [RESC1005-STAR]
U8  EP3C40F780C8N  [FBGA780-2]  (parts A,B,C,D,E,F,G,H,I of 13)
U70  CY2305 Zero-delay Buffer  [SOIC127P600-8]

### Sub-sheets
PULLDOWN = PULLDNx3.SCHDOC: EXT, INT (harness RGB_LED)
PULLDOWN = PULLDNx3.SCHDOC: EXT, INT (harness RGB_LED)
PULLDOWN = PULLDNx3.SCHDOC: EXT, INT (harness RGB_LED)
PULLDOWN = PULLDNx3.SCHDOC: EXT, INT (harness RGB_LED)
PULLDOWN = PULLDNx3.SCHDOC: EXT, INT (harness RGB_LED)
PULLDOWN = PULLDNx3.SCHDOC: EXT, INT (harness RGB_LED)
PULLDOWN = PULLDNx3.SCHDOC: EXT, INT (harness RGB_LED)
PULLDOWN = PULLDNx3.SCHDOC: EXT, INT (harness RGB_LED)
U_FPGA_Power = FPGA_NonIO.SchDoc: TMS (in), CONF_DONE (bidir), DCLK (bidir), TCK (in), nSTATUS (in), TDI (in), nCONFIG (in), TDO (out)
USER_DECOUPLING_CAPS_1V2 = FPGA_Bypass_1V2.SCHDOC: no entries
USER_DECOUPLING_CAPS_3V3 = FPGA_Bypass_3V3.SCHDOC: no entries

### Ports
ADC (harness ADC_SPI), BUZZER (out), CODEC (harness AUDIO_DIGITAL), DAC (harness DAC_SPI), DAU_RESET_SW (in), DB_CLOCKS (harness DB_CLOCKS), DB_JTAG (harness HARDSOFT_JTAG), DB_PROGRAM (harness DAU_CTRL), DB_SPI (harness DB_SPI), DBSD (harness SD), DBUSB (harness USB_INTF), DIP (harness SW8), ETH (harness Ethernet), EXT_A (harness PBIO), I2C (harness I2C), ISP176X (harness ISP176X), KEYBOARD (harness PS2), MEM_COMMON (harness HOSTMEMORY), MIDI (harness MIDI_INT), MOUSE (harness PS2), ONE_WIRE_DB_PB (bidir), PROTOTYPE (harness IO36), PWM (harness PWM4), RELAY (harness RELAY4), RS232 (harness RS232_INT), RS485 (harness RS485_INT), SPAREIO (harness SPAREIO), SPDIF (harness SPDIF), SRAM1 (harness SRAM-256Kx16), SRAM2 (harness SRAM-256Kx16), STATUS_LED (out), SW (harness SW5), TFT_IO (harness TFT_IO), TFT_TSC (harness TFT_TSC), USER_LEDS (harness USER_LEDS), USERIO (harness IO36), VGA (harness VGA)

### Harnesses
SRAM-256Kx16: A[18..0], D[15..0], NCS, NWE, NOE, NBHE, NBLE
HOSTMEMORY: BUS_A[24..1], BUS_D[31..0], BUS_NOE, BUS_NWE, BUS_NBE[3..0], BUS_SRAM_NCS, BUS_FLASH_NCS, BUS_SDRAM_NCS, BUS_SDRAM_CKE, BUS_SDRAM_CLK, BUS_SDRAM_NCAS, BUS_SDRAM_NRAS, BUS_FLASH_NRESET, BUS_FLASH_NBUSY
DAU_CTRL: DIN, DONE, INSTALLED, ID[3..0], CCLK, PROGRAM, M[2..0], INIT, PROG_PWR_ON, PROG_CLK
SW5: D[4..0]
PS2: DATA, CLOCK
RS232_INT: RXD, TXD, RTS, CTS
IO36: IO[35..0]
I2C: SCL, SDA
RGB_LED: GREEN, RED, BLUE
AUDIO_DIGITAL: I2S_DOUT, I2S_DIN, I2S_BCLK, I2S_WCLK, I2S_MCLK, SPI_CLK, SPI_DIN, SPI_DOUT, SPI_CS_N
SW8: D[7..0]
SD: CLK, CMD, DAT[3..0], DETECT, PROTECT
Ethernet: E_RXC, E_TXC, E_TXD[3..0], E_TXEN, E_COL, E_RXD[3..0], E_RXDV, E_RESETB_E, E_MDIO, E_MDC, E_RXER, E_CRS
SPDIF: IN, OUT
VGA: RED[7..0], GREEN[7..0], BLUE[7..0], VGA_CLK, VGA_VSYNC, VGA_HSYNC
RELAY4: RELAY[3..0]
ADC_SPI: CS, CLK, DIN, DOUT
DAC_SPI: CS, CLK, DIN
MIDI_INT: MIDI_TX, MIDI_RX
JTAG: TMS, TDO, TDI, TCK
HARDSOFT_JTAG: HARD, SOFT
DB_CLOCKS: REF_CLK, FPGA_CLK, FPGA_CLK1
PWM4: PWM0, PWM1, PWM2, PWM3
RS485_INT: TX_EN, RXD, RX_EN, TXD
DB_SPI: MODE, SEL, CLK, DIN, DOUT
TFT_IO: CS, RS, WR, RD, RESET, DB[17..0], BL, IR38KTX, IR38KRX
USER_LEDS: LED0, LED1, LED2, LED3, LED4, LED5, LED6, LED7
PBIO: D[49..0]
USB_INTF: READY, INT_N, SLOE, FIFOADR2, FIFOADR0, FIFOADR1, PKTEND, FLAGD_CS_N, FLAGA, FLAGB, FLAGC, WR_N, RD_N, D[15..0], RESET_N, IFCLK, XTALIN, VBUS, XTALOUT
ISP176X: BUS_A[17..1], BUS_D[31..0], BUS_NREAD, BUS_NCS, BUS_DMA_REQ, BUS_DMA_ACK, BUS_NIRQ, BUS_NWRITE, ISP176X_NRESET
SPAREIO: 1, 2, 3, 4
TFT_TSC: CLK, CS_N, DIN, DOUT, BUSY, TFT_INT

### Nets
3V3: NT2#2.2(Net2) R1#2.2 R2#2.2 R3#2.2 R4#2.2 R273.2 R275.2 R277.1 R278.2 R283.1 U70.6(VDD)
GND: NT3#3.2(Net2) NT4.2(Net2) NT5.2(Net2) R272.1 R274.1 U70.4(GND)
485_RX_EN: U8.B3(IO,_DIFFIO_T10n) ; port RS485.RX_EN
485_RXD: U8.E8(IO,_DIFFIO_T14p) ; port RS485.RXD
485_TX_EN: U8.H8(IO,_DIFFIO_T1n) ; port RS485.TX_EN
485_TXD: U8.C3(IO) ; port RS485.TXD
ADC_CLK: U8.F14(IO,_DIFFIO_T22p) ; port ADC.CLK
ADC_CS: U8.G1(IO,_DIFFIO_L20n) ; port ADC.CS
ADC_DIN: U8.G2(IO,_DIFFIO_L20p,_(DQ0L)/(DQ1L)/(DQ1L)) ; port ADC.DIN
ADC_DOUT: U8.L3(IO,_DIFFIO_L17n) ; port ADC.DOUT
BUS_A1: U8.AF17(IO,_DIFFIO_B32n,_(DQS4B/CQ5B,DPCLK4)/(DQS4B/CQ5B,DPCLK4)/(DQS4B/CQ5B,DPCLK4))
BUS_A2: U8.C13(IO,_DIFFIO_T26n,_(DQ5T)/(DQ3T)/(DQ5T))
BUS_A3: U8.C15(IO,_DIFFIO_T27n,_(PADD13))
BUS_A4: U8.A17(IO,_DIFFIO_T29n,_(PADD11),__/(DQ5T)/(DQ5T))
BUS_A5: U8.C17(IO,_DIFFIO_T38n,_(PADD3),_(DQ4T)/(DQ5T)/(DQ5T))
BUS_A6: U8.C19(IO,_DIFFIO_T39p,_(DQ4T)/(DQ5T)/(DQ5T))
BUS_A7: U8.K21(IO,_DIFFIO_R19p)
BUS_A8: U8.H26(IO,_DIFFIO_R26n)
BUS_A9: U8.K26(IO,_DIFFIO_R10p,_(DQ2R)/(DQ1R)/(DQ1R))
BUS_A10: U8.P2(IO,_DIFFIO_L25p)
BUS_A11: U8.L26(IO,_DIFFIO_R14p,_(DM2R)/(DM1R0/BWS#1R0)/(DM1R0/BWS#1R0))
BUS_A12: U8.AE26(IO,_DIFFIO_R54n)
BUS_A13: U8.L28(IO,_DIFFIO_R18p,_(DQ0R)/(DQ1R)/(DQ1R))
BUS_A14: U8.K28(IO,_DIFFIO_R16p,_(DQ0R)/(DQ1R)/(DQ1R))
BUS_A15: U8.AE27(IO,_DIFFIO_R54p)
BUS_A16: U8.AH25(IO,_DIFFIO_B49n,_(DQ0B)/_/_)
BUS_A17: U8.AD12(IO,_DIFFIO_B2p)
BUS_A18: U8.C18(IO,_DIFFIO_T41n,_(PADD1),__/(DQ5T)/(DQ5T))
BUS_A19: U8.B18(IO,_DIFFIO_T35p,_(PADD8),_(DQ4T)/(DQ5T)/(DQ5T))
BUS_A20: U8.J26(IO)
BUS_A21: U8.H25(IO,_DIFFIO_R19n)
BUS_A22: U8.M23(IO,_DIFFIO_R22p)
BUS_A23: U8.T22(IO,_DIFFIO_R32n,_(DEV_OE))
BUS_A24: U8.M27(IO,_(DQ0R)/(DQ1R)/(DQ1R))
BUS_D0: U8.N26(IO,_DIFFIO_R23n,_(DQS0R/CQ1R,DPCLK7)/(DQS0R/CQ1R,DPCLK7)/(DQS0R/CQ1R,DPCLK7))
BUS_D1: U8.R26(IO,_DIFFIO_R31n,_(DQ1R)/(DQ3R)/(DQ1R))
BUS_D2: U8.P28(IO,_DIFFIO_R24n,_(nCEO))
BUS_D3: U8.U28(IO,_DIFFIO_R36p,_(DQ1R)/(DQ3R)/(DQ1R))
BUS_D4: U8.U25(IO,_DIFFIO_R30p)
BUS_D5: U8.V25(IO,_DIFFIO_R38n,_(DQ1R)/(DQ3R)/(DQ1R))
BUS_D6: U8.Y26(IO,_DIFFIO_R43p,_(DQ1R)/(DQ3R)/(DQ1R))
BUS_D7: U8.G26(IO,_DIFFIO_R9n)
BUS_D8: U8.K27(IO,_DIFFIO_R15p,_(DQ0R)/(DQ1R)/(DQ1R))
BUS_D9: U8.V28(IO,_DIFFIO_R40p,_(DQ1R)/(DQ3R)/(DQ1R))
BUS_D10: U8.U27(IO,_DIFFIO_R37p)
BUS_D11: U8.R23(IO,_DIFFIO_R29n)
BUS_D12: U8.R24(IO,_VREFB5N0)
BUS_D13: U8.T21(IO,_DIFFIO_R32p,_(DEV_CLRn))
BUS_D14: U8.P27(IO,_DIFFIO_R24p,_(CLKUSR))
BUS_D15: U8.P26(IO,_DIFFIO_R27n,_(INIT_DONE))
BUS_D16: U8.R28(IO,_DIFFIO_R30n,_(DM0R)/(DM1R1/BWS#1R1)/(DM1R1/BWS#1R1))
BUS_D17: U8.T26(IO,_DIFFIO_R35p)
BUS_D18: U8.U26(IO,_DIFFIO_R45p)
BUS_D19: U8.V27(IO,_DIFFIO_R39p)
BUS_D20: U8.W27(IO,_DIFFIO_R41n,_(DQ1R)/(DQ3R)/(DQ1R))
BUS_D21: U8.AA26(IO,_DIFFIO_R45n,_(DQ3R)/(DQ3R)/(DQ1R))
BUS_D22: U8.AB28(IO,_DIFFIO_R44n,_(DM1R/BWS#1R)/(DM3R0/BWS#3R0)/(DM1R2/BWS#1R2))
BUS_D23: U8.AB26(IO,_DIFFIO_R46p,_(DQ3R)/(DQ3R)/(DQ1R))
BUS_D24: U8.F28(IO,_DIFFIO_R8n,_(nAVD),_(DQ2R)/(DQ1R)/(DQ1R))
BUS_D25: U8.W22(IO,_DIFFIO_R48p)
BUS_D26: U8.V24(IO,_DIFFIO_R37n)
BUS_D27: U8.V21(IO,_DIFFIO_R43n)
BUS_D28: U8.V22(IO)
BUS_D29: U8.U22(IO,_DIFFIO_R34p)
BUS_D30: U8.R25(IO,_DIFFIO_R31p)
BUS_D31: U8.P25(IO,_DIFFIO_R27p,_(CRC_ERROR))
BUS_FLASH_NBUSY: U8.D25(IO,_DIFFIO_R2n) ; port MEM_COMMON.BUS_FLASH_NBUSY
BUS_FLASH_NCS: U8.C27(IO,_DIFFIO_R4n,_(PADD20),_(DQS2R/CQ3R,CDPCLK5)/(DQS2R/CQ3R,CDPCLK5)/(DQS2R/CQ3R,CDPCLK5)) ; port MEM_COMMON.BUS_FLASH_NCS
BUS_FLASH_NRESET: U8.P21(IO) ; port MEM_COMMON.BUS_FLASH_NRESET
BUS_ISP176X_DACK: U8.AF13(IO,_DIFFIO_B20n) ; port ISP176X.BUS_DMA_ACK
BUS_ISP176X_DREQ: U8.AH19(IO,_DIFFIO_B35n,_(DM2B)/(DM5B0/BWS#5B0)/(DM5B0/BWS#5B0)) ; port ISP176X.BUS_DMA_REQ
BUS_ISP176X_NCS: U8.AB14(IO,_DIFFIO_B24n) ; port ISP176X.BUS_NCS
BUS_ISP176X_NIRQ: U8.AF16(IO,_DIFFIO_B32p,_(DQ4B)/(DQ5B)/(DQ5B)) ; port ISP176X.BUS_NIRQ
BUS_NBE0: U8.W21(IO,_DIFFIO_R47p)
BUS_NBE1: U8.A25(IO,_DIFFIO_T49p,_(DQS0T/CQ1T,CDPCLK6)/(DQS0T/CQ1T,CDPCLK6)/(DQS0T/CQ1T,CDPCLK6))
BUS_NBE2: U8.AC27(IO,_DIFFIO_R46n,_(DQ3R)/(DQ3R)/(DQ1R))
BUS_NBE3: U8.V26(IO)
BUS_NOE: U8.AF12(IO,_DIFFIO_B19n) ; port MEM_COMMON.BUS_NOE, port ISP176X.BUS_NREAD
BUS_NWE: U8.G7(IO,_DIFFIO_L6n) ; port MEM_COMMON.BUS_NWE, port ISP176X.BUS_NWRITE
BUS_SDRAM_CKE: R274.2 R275.1 U8.Y23(IO,_DIFFIO_R50p) ; port MEM_COMMON.BUS_SDRAM_CKE
BUS_SDRAM_CLK: NT3#2.2(Net2) R272.2 R273.1 U8.AE5(IO,_PLL1_CLKOUTp) ; port MEM_COMMON.BUS_SDRAM_CLK
BUS_SDRAM_FEEDBACK: NT3#2.1(Net1) U8.J1(CLK1,_DIFFCLK_0n)
BUS_SDRAM_NCAS: U8.AC26(IO,_DIFFIO_R49p) ; port MEM_COMMON.BUS_SDRAM_NCAS
BUS_SDRAM_NCS: U8.AA21(IO,_DIFFIO_R56n) ; port MEM_COMMON.BUS_SDRAM_NCS
BUS_SDRAM_NRAS: U8.AC24(IO,_DIFFIO_R55p) ; port MEM_COMMON.BUS_SDRAM_NRAS
BUS_SRAM_NCS: U8.D13(IO,_DIFFIO_T26p,_(DQ5T)/(DQ3T)/(DQ5T)) ; port MEM_COMMON.BUS_SRAM_NCS
BUZZER: U8.AA7(IO,_DIFFIO_L40p) ; port BUZZER
CODECI2S_BCLK: U8.K13(IO,_DIFFIO_T22n) ; port CODEC.I2S_BCLK
CODECI2S_DIN: U8.AB8(IO) ; port CODEC.I2S_DIN
CODECI2S_DOUT: U8.AE6(IO,_DIFFIO_B2n,_(DM1B)/_/_) ; port CODEC.I2S_DOUT
CODECI2S_MCLK: U8.G14(IO,_VREFB8N0) ; port CODEC.I2S_MCLK
CODECI2S_WCLK: U8.AF14(IO,_DIFFIO_B27n) ; port CODEC.I2S_WCLK
CODECSPI_CLK: U8.D15(IO,_DIFFIO_T27p,_(PADD14),_(DQ5T)/(DQ3T)/(DQ5T)) ; port CODEC.SPI_CLK
CODECSPI_CS: U8.W4(IO,_DIFFIO_L36n) ; port CODEC.SPI_CS_N
CODECSPI_DIN: U8.Y4(IO,_DIFFIO_L42p,_(DQ3L)/(DQ3L)/(DQ1L)) ; port CODEC.SPI_DIN
CODECSPI_DOUT: U8.AG4(IO,_DIFFIO_B4p) ; port CODEC.SPI_DOUT
CONF_DONE: R22#1.2 ; sheet U_FPGA_Power/CONF_DONE
DAC_CLK: U8.C14(IO,_DIFFIO_T25n,_(DQ5T)/(DQ3T)/(DQ5T)) ; port DAC.CLK
DAC_CS: U8.F3(IO,_DIFFIO_L7n,_(DQ2L)/(DQ1L)/(DQ1L)) ; port DAC.CS
DAC_DIN: U8.K3(IO,_DIFFIO_L13n) ; port DAC.DIN
DAU_FPGA_CLK1: U8.AG15(CLK13,_DIFFCLK_7p) U8.B15(CLK9,_DIFFCLK_5p) U8.J2(CLK0,_DIFFCLK_0p) ; port DB_CLOCKS.FPGA_CLK1
DAU_RESET_SW: U8.AG12(IO,_DIFFIO_B26p,_(DQ5B)/(DQ3B)/(DQ5B)) ; port DAU_RESET_SW
DAU_SPI_CLK: U8.AE14(IO,_DIFFIO_B27p) ; port DB_SPI.CLK
DAU_SPI_DIN: U8.AG23(IO,_DIFFIO_B50p) ; port DB_SPI.DOUT
DAU_SPI_DOUT: U8.AB27(IO,_DIFFIO_R44p,_(DQ1R)/(DQ3R)/(DQ1R)) ; port DB_SPI.DIN
DAU_SPI_MODE: U8.AF27(IO,_(DQS3R/CQ3R#,CDPCLK4)/(DQS3R/CQ3R#,CDPCLK4)/(DQS3R/CQ3R#,CDPCLK4)) ; port DB_SPI.MODE
DAU_SPI_SEL: U8.AE25(IO,_DIFFIO_B47n,_(DQ0B)/_/_) ; port DB_SPI.SEL
DB_REF_CLK: U70.1(REF) ; port DB_CLOCKS.REF_CLK
DCLK: R20#1.2 ; sheet U_FPGA_Power/DCLK
DIP0: U8.AF11(IO,_DIFFIO_B21n,_(DQS5B/CQ5B#,DPCLK3)/(DQS5B/CQ5B#,DPCLK3)/(DQS5B/CQ5B#,DPCLK3))
DIP1: U8.AC11(IO,_DIFFIO_B1p)
DIP2: U8.AE10(IO,_DIFFIO_B16p,_(DQS3B/CQ3B#,DPCLK2)/(DQS3B/CQ3B#,DPCLK2)/(DQS3B/CQ3B#,DPCLK2))
DIP3: U8.AF10(IO,_DIFFIO_B21p,_(DQ5B)/(DQ3B)/(DQ5B))
DIP4: U8.AG8(IO,_DIFFIO_B15p,_(DQ3B)/(DQ3B)/(DQ5B))
DIP5: U8.AE8(IO,_DIFFIO_B5n)
DIP6: U8.AC8(IO,_DIFFIO_B14p,_(DQ3B)/(DQ3B)/(DQ5B))
DIP7: U8.AC7(IO,_DIFFIO_L48n)
E_COL: U8.J3(IO,_DIFFIO_L19n,_(DQ0L)/(DQ1L)/(DQ1L)) ; port ETH.E_COL
E_CRS: U8.A6(IO,_DIFFIO_T8n) ; port ETH.E_CRS
E_MDC: U8.C2(IO,_DIFFIO_L1n,_(DQ2L)/(DQ1L)/(DQ1L)) ; port ETH.E_MDC
E_MDIO: U8.G6(IO,_DIFFIO_L4p,_(nRESET),_(DQ2L)/(DQ1L)/(DQ1L)) ; port ETH.E_MDIO
E_RESETB_E: U8.F5(IO,_DIFFIO_L8p,_(DQ2L)/(DQ1L)/(DQ1L)) ; port ETH.E_RESETB_E
E_RXC: U8.G15(IO,_VREFB7N3) ; port ETH.E_RXC
E_RXD0: U8.D2(IO,_DIFFIO_L2p,_(DQ2L)/(DQ1L)/(DQ1L))
E_RXD1: U8.D1(IO,_DIFFIO_L2n,_(DQ2L)/(DQ1L)/(DQ1L))
E_RXD2: U8.E3(IO,_DIFFIO_L7p,_(DQS2L/CQ3L,CDPCLK0)/(DQS2L/CQ3L,CDPCLK0)/(DQS2L/CQ3L,CDPCLK0))
E_RXD3: U8.H5(IO,_DIFFIO_L18n)
E_RXDV: U8.E4(IO,_DIFFIO_L3n) ; port ETH.E_RXDV
E_RXER: U8.B8(IO,_DIFFIO_T17n) ; port ETH.E_RXER
E_TXC: U8.J5(IO,_DIFFIO_L6p) ; port ETH.E_TXC
E_TXD0: U8.G4(IO,_DIFFIO_L9p,_(DQ2L)/(DQ1L)/(DQ1L))
E_TXD1: U8.F1(IO,_DIFFIO_L12n,_(DQ0L)/(DQ1L)/(DQ1L))
E_TXD2: U8.H6(IO,_DIFFIO_L18p)
E_TXD3: U8.G5(IO,_DIFFIO_L4n,_(DQ2L)/(DQ1L)/(DQ1L))
E_TXEN: U8.G3(IO,_DIFFIO_L9n) ; port ETH.E_TXEN
EXTEND_A0: U8.AA13(IO,_DIFFIO_B11n)
EXTEND_A1: U8.AH10(IO,_DIFFIO_B17n)
EXTEND_A2: U8.AF9(IO,_DIFFIO_B18p,_(DQ3B)/(DQ3B)/(DQ5B))
EXTEND_A3: U8.AG10(IO,_DIFFIO_B22p,_(DQ5B)/(DQ3B)/(DQ5B))
EXTEND_A4: U8.AH8(IO,_DIFFIO_B16n,_(DQ3B)/(DQ3B)/(DQ5B))
EXTEND_A5: U8.AH7(IO,_(DQ3B)/(DQ3B)/(DQ5B))
EXTEND_A6: U8.AG7(IO,_DIFFIO_B13p,_(DQ3B)/(DQ3B)/(DQ5B))
EXTEND_A7: U8.AF8(IO,_DIFFIO_B19p,_(DM5B/BWS#5B)/(DM3B0/BWS#3B0)/(DM5B2/BWS#5B2))
EXTEND_A8: U8.AB12(IO,_DIFFIO_B3n)
EXTEND_A9: U8.AF7(IO,_DIFFIO_B17p,_(DQ3B)/(DQ3B)/(DQ5B))
EXTEND_A10: U8.AF2(IO,_DIFFIO_L50n,_(DM3L/BWS#3L)/(DM3L1/BWS#3L1)/(DM1L3/BWS#1L3))
EXTEND_A11: U8.AF6(IO,_(DQ1B)/_/_)
EXTEND_A12: U8.AG6(IO,_DIFFIO_B10p,_(DQ1B)/_/_)
EXTEND_A13: U8.AH4(IO,_DIFFIO_B8n,_(DQ1B)/_/_)
EXTEND_A14: U8.AE1(IO,_DIFFIO_L49p)
EXTEND_A15: U8.AD7(IO,_DIFFIO_B6p,_(DQS1B/CQ1B#,CDPCLK2)/(DQS1B/CQ1B#,CDPCLK2)/(DQS1B/CQ1B#,CDPCLK2))
EXTEND_A16: U8.AB5(IO,_DIFFIO_L51n)
EXTEND_A17: U8.AF5(IO,_PLL1_CLKOUTn)
EXTEND_A18: U8.AH3(IO,_DIFFIO_B7p,_(DQ1B)/_/_)
EXTEND_A19: U8.AG3(IO,_DIFFIO_B4n,_(DQ1B)/_/_)
EXTEND_A20: U8.AF3(IO,_DIFFIO_L54n)
EXTEND_A21: U8.AE4(IO,_DIFFIO_L54p)
EXTEND_A22: U8.AC2(IO,_DIFFIO_L43n,_(DQ3L)/(DQ3L)/(DQ1L))
EXTEND_A23: U8.AE3(IO,_(DQS3L/CQ3L#,CDPCLK1)/(DQS3L/CQ3L#,CDPCLK1)/(DQS3L/CQ3L#,CDPCLK1))
EXTEND_A24: U8.AE2(IO,_DIFFIO_L49n,_(DQ3L)/(DQ3L)/(DQ1L))
EXTEND_A25: U8.Y7(IO,_DIFFIO_L41n)
EXTEND_A26: U8.AD1(IO,_DIFFIO_L46n)
EXTEND_A27: U8.AC1(IO,_DIFFIO_L44n,_(DQ3L)/(DQ3L)/(DQ1L))
EXTEND_A28: U8.AB3(IO,_DIFFIO_L47p,_(DQ3L)/(DQ3L)/(DQ1L))
EXTEND_A29: U8.AB2(IO,_DIFFIO_L34p,_(DQS1L/CQ1L#,DPCLK1)/(DQS1L/CQ1L#,DPCLK1)/(DQS1L/CQ1L#,DPCLK1))
EXTEND_A30: U8.AC3(IO,_DIFFIO_L45n,_(DQ3L)/(DQ3L)/(DQ1L))
EXTEND_A31: U8.AD3(IO,_DIFFIO_L52n)
EXTEND_A32: U8.W8(IO,_DIFFIO_L44p)
EXTEND_A33: U8.V8(IO,_VREFB2N2)
EXTEND_A34: U8.W10(IO,_DIFFIO_B7n)
EXTEND_A35: U8.Y3(IO,_DIFFIO_L42n)
EXTEND_A36: U8.W3(IO,_DIFFIO_L36p)
EXTEND_A37: U8.V3(IO,_DIFFIO_L33p)
EXTEND_A38: U8.AD5(IO,_DIFFIO_L53n)
EXTEND_A39: U8.AB4(IO,_VREFB2N3)
EXTEND_A40: U8.AA6(IO,_DIFFIO_L40n)
EXTEND_A41: U8.AB7(IO,_DIFFIO_L48p)
EXTEND_A42: U8.W2(IO,_DIFFIO_L35p,_(DQ1L)/(DQ3L)/(DQ1L))
EXTEND_A43: U8.U8(IO,_RDN1)
EXTEND_A44: U8.V2(IO,_DIFFIO_L33n,_(DQ1L)/(DQ3L)/(DQ1L))
EXTEND_A45: U8.AA5(IO,_DIFFIO_L50p)
EXTEND_A46: U8.U7(IO,_RUP1)
EXTEND_A47: U8.T8(IO,_VREFB2N0)
EXTEND_A48: U8.U3(IO,_DIFFIO_L27p,_(DM0L)/(DM1L1/BWS#1L1)/(DM1L1/BWS#1L1))
EXTEND_A49: U8.V6(IO,_DIFFIO_L37p)
FPGA_CCLK: R20#1.1 ; port DB_PROGRAM.CCLK
FPGA_CLK: U8.A14(CLK10,_DIFFCLK_4n) U8.A15(CLK8,_DIFFCLK_5n) U8.J27(CLK4,_DIFFCLK_2p) ; port DB_CLOCKS.FPGA_CLK
FPGA_DIN: R14#1.2 ; port DB_PROGRAM.DIN
FPGA_DONE: R4#2.1 R22#1.1 ; port STATUS_LED, port DB_PROGRAM.DONE
FPGA_ID0: NT2#2.1(Net1)
FPGA_ID1: NT3#3.1(Net1)
FPGA_ID2: NT4.1(Net1)
FPGA_ID3: NT5.1(Net1)
FPGA_INIT: R3#2.1 R18#1.2 ; port DB_PROGRAM.INIT
FPGA_M0: R23#1.1
FPGA_PROGRAM: R1#2.1 R24#1.1 ; port DB_PROGRAM.PROGRAM
FPGA_TCK: R9#1.1 ; harness JTAG.TCK
FPGA_TDI: R12#1.1 ; harness JTAG.TDI
FPGA_TDO: R2#2.1 R10#1.1 ; harness JTAG.TDO
FPGA_TMS: R8#1.1 ; harness JTAG.TMS
HOST_SPARE1: R23#1.2 U8.AC22(IO,_DIFFIO_B53n)
IO0: U8.N4(IO,_DIFFIO_L22p)
IO1: U8.R6(IO,_DIFFIO_L28n)
IO2: U8.M8(IO,_DIFFIO_L16p)
IO3: U8.R4(IO,_DIFFIO_L29p,_(DQ1L)/(DQ3L)/(DQ1L))
IO4: U8.M4(IO)
IO5: U8.N3(IO,_DIFFIO_L22n)
IO6: U8.L7(IO,_DIFFIO_L15n)
IO7: U8.R5(IO,_DIFFIO_L31n,_(DQ1L)/(DQ3L)/(DQ1L))
IO8: U8.M5(IO,_VREFB1N3)
IO9: U8.T9(IO,_DIFFIO_L43p)
IO10: U8.L8(IO,_DIFFIO_L15p)
IO11: U8.M7(IO,_DIFFIO_L16n)
IO12: U8.L1(IO,_DIFFIO_L23n,_(DQ0L)/(DQ1L)/(DQ1L))
IO13: U8.M1(IO,_DIFFIO_L24n,_(DQ0L)/(DQ1L)/(DQ1L))
IO14: U8.L4(IO,_DIFFIO_L17p)
IO15: U8.M9(IO)
IO16: U8.L5(IO,_VREFB1N1)
IO17: U8.M2(IO,_DIFFIO_L24p)
IO18: U8.J4(IO,_DIFFIO_L19p)
IO19: U8.L2(IO,_DIFFIO_L23p)
IO20: U8.J7(IO,_DIFFIO_L11n)
IO21: U8.K7(IO,_DIFFIO_L14p)
IO22: U8.J6(IO,_DIFFIO_L10n)
IO23: U8.L6(IO,_DIFFIO_L14n)
IO24: U8.H4(IO,_DIFFIO_L5p)
IO25: U8.K4(IO,_DIFFIO_L13p)
IO26: U8.R7(IO,_DIFFIO_L29n)
IO27: U8.K2(IO,_(DQS0L/CQ1L,DPCLK0)/(DQS0L/CQ1L,DPCLK0)/(DQS0L/CQ1L,DPCLK0))
IO28: U8.U6(IO,_DIFFIO_L39n,_(DQ3L)/(DQ3L)/(DQ1L))
IO29: U8.P1(IO,_DIFFIO_L25n,_(DQ0L)/(DQ1L)/(DQ1L))
IO30: U8.U4(IO,_DIFFIO_L31p)
IO31: U8.R1(IO,_DIFFIO_L26n,__/(DQ1L)/(DQ1L))
IO32: U8.V9(IO)
IO33: U8.U5(IO,_DIFFIO_L37n)
IO34: U8.V5(IO,_DIFFIO_L39p)
IO35: U8.AA8(IO,_DIFFIO_L41p)
IR38KRX: U8.AA15(IO,_VREFB4N3) ; port TFT_IO.IR38KRX
IR38KTX: U8.AB15(IO,_DIFFIO_B28p) ; port TFT_IO.IR38KTX
ISP176X_RST: U8.AH11(IO,_DIFFIO_B24p,_(DQ5B)/(DQ3B)/(DQ5B)) ; port ISP176X.ISP176X_NRESET
KBCLOCK: U8.AE7(IO,_DIFFIO_B5p) ; port KEYBOARD.CLOCK
KBDATA: U8.AD8(IO,_DIFFIO_B9n,_(DQ1B)/_/_) ; port KEYBOARD.DATA
LED0_B: U8.R3(IO,_DIFFIO_L28p,_(DQ1L)/(DQ3L)/(DQ1L)) ; sheet PULLDOWN/INT.BLUE
LED0_G: U8.U1(IO,_DIFFIO_L32p,_(DQ1L)/(DQ3L)/(DQ1L)) ; sheet PULLDOWN/INT.GREEN
LED0_R: U8.R2(IO,_DIFFIO_L26p,_(DQ0L)/(DQ1L)/(DQ1L)) ; sheet PULLDOWN/INT.RED
LED1_B: U8.V4(IO,_DIFFIO_L32n,_(DQ1L)/(DQ3L)/(DQ1L)) ; sheet PULLDOWN/INT.BLUE
LED1_G: U8.T3(IO,_DIFFIO_L30n) ; sheet PULLDOWN/INT.GREEN
LED1_R: U8.W9(IO) ; sheet PULLDOWN/INT.RED
LED2_B: U8.AD10(IO,_DIFFIO_B12n,_(DQ3B)/(DQ3B)/(DQ5B)) ; sheet PULLDOWN/INT.BLUE
LED2_G: U8.AG11(IO,_DIFFIO_B23n,_(DQ5B)/(DQ3B)/(DQ5B)) ; sheet PULLDOWN/INT.GREEN
LED2_R: U8.AC10(IO,_DIFFIO_B9p) ; sheet PULLDOWN/INT.RED
LED3_B: U8.AD11(IO,_DIFFIO_B1n) ; sheet PULLDOWN/INT.BLUE
LED3_G: U8.AC12(IO,_DIFFIO_B8p) ; sheet PULLDOWN/INT.GREEN
LED3_R: U8.Y13(IO,_DIFFIO_B13n) ; sheet PULLDOWN/INT.RED
LED4_B: U8.AB23(IO,_RDN3) ; sheet PULLDOWN/INT.BLUE
LED4_G: U8.AD26(IO,_DIFFIO_R52p,_(DQ3R)/(DQ3R)/(DQ1R)) ; sheet PULLDOWN/INT.GREEN
LED4_R: U8.AB24(IO,_DIFFIO_R55n,_(DM3R/BWS#3R)/(DM3R1/BWS#3R1)/(DM1R3/BWS#1R3)) ; sheet PULLDOWN/INT.RED
LED5_B: U8.AB20(IO,_VREFB4N0) ; sheet PULLDOWN/INT.BLUE
LED5_G: U8.AA24(IO,_VREFB5N3) ; sheet PULLDOWN/INT.GREEN
LED5_R: U8.AB25(IO,_DIFFIO_R40n) ; sheet PULLDOWN/INT.RED
LED6_B: U8.AA25(IO,_DIFFIO_R39n) ; sheet PULLDOWN/INT.BLUE
LED6_G: U8.AA23(IO,_DIFFIO_R51p) ; sheet PULLDOWN/INT.GREEN
LED6_R: U8.W26(IO,_DIFFIO_R42p,_(DQ1R)/(DQ3R)/(DQ1R)) ; sheet PULLDOWN/INT.RED
LED7_B: U8.AD27(IO,_DIFFIO_R49n,_(DQ3R)/(DQ3R)/(DQ1R)) ; sheet PULLDOWN/INT.BLUE
LED7_G: U8.AC28(IO,_DIFFIO_R47n,_(DQ3R)/(DQ3R)/(DQ1R)) ; sheet PULLDOWN/INT.GREEN
LED7_R: U8.Y22(IO,_DIFFIO_R53n) ; sheet PULLDOWN/INT.RED
MIDI_RX: U8.C4(IO,_DIFFIO_T1p,_(DQ1T)/_/_) ; port MIDI.MIDI_RX
MIDI_TX: U8.D6(IO,_(DQ1T)/_/_) ; port MIDI.MIDI_TX
MOUSECLOCK: U8.AE9(IO,_DIFFIO_B20p,_(DQ5B)/(DQ3B)/(DQ5B)) ; port MOUSE.CLOCK
MOUSEDATA: U8.Y10(IO,_VREFB3N3) ; port MOUSE.DATA
NC1: U8.Y2(CLK2,_DIFFCLK_1p)
NC2: U8.Y1(CLK3,_DIFFCLK_1n)
NC3: U8.Y28(CLK7,_DIFFCLK_3n)
NC4: U8.AH15(CLK12,_DIFFCLK_7n)
NC5: U8.AG14(CLK15,_DIFFCLK_6p)
NC6: U8.F4(IO,_DIFFIO_L8n,_(DATA1,_ASDO))
NC7: U8.E2(IO,_DIFFIO_L10p,_(FLASH_nCE,_nCSO))
nCONFIG: R24#1.2 ; sheet U_FPGA_Power/nCONFIG
NEXUS_TCK: U8.Y27(CLK6,_DIFFCLK_3p) ; harness JTAG.TCK
NEXUS_TDI: U8.AD21(IO) ; harness JTAG.TDI
NEXUS_TDO: U8.AC21(IO,_DIFFIO_B48p) ; harness JTAG.TDO
NEXUS_TMS: U8.AE22(IO,_DIFFIO_B52n) ; harness JTAG.TMS
nSTATUS: R18#1.1 ; sheet U_FPGA_Power/nSTATUS
ONE_WIRE_DB_PB: R283.2 U8.U2(IO,_DIFFIO_L27n) ; port ONE_WIRE_DB_PB
P0_PWM: U8.F8(IO,_DIFFIO_T9n) ; port PWM.PWM0
P1_PWM: U8.B7(IO,_DIFFIO_T11p,_(DATA5),_(DQ3T)/(DQ3T)/(DQ5T)) ; port PWM.PWM1
P2_PWM: U8.C6(IO,_DIFFIO_T2p,_(DQ1T)/_/_) ; port PWM.PWM2
P3_PWM: U8.B4(IO,_DIFFIO_T3p,_(DATA12),_(DQS1T/CQ1T#,CDPCLK7)/(DQS1T/CQ1T#,CDPCLK7)/(DQS1T/CQ1T#,CDPCLK7)) ; port PWM.PWM3
REF_CLKa: R314.1 U8.AH14(CLK14,_DIFFCLK_6n) U8.J28(CLK5,_DIFFCLK_2n)
REF_CLKb: R213.1 U8.B14(CLK11,_DIFFCLK_4p)
RELAY0: U8.C7(IO,_DIFFIO_T4n,_(DATA10),_(DQ1T)/_/_)
RELAY1: U8.C11(IO,_DIFFIO_T7n,_(DATA7),_(DQ3T)/(DQ3T)/(DQ5T))
RELAY2: U8.B12(IO,_DIFFIO_T23p)
RELAY3: U8.A12(IO,_DIFFIO_T23n,_(DQ5T)/(DQ3T)/(DQ5T))
RS232_CTS: U8.K1(IO,_DIFFIO_L21n,_(DQ0L)/(DQ1L)/(DQ1L)) ; port RS232.CTS
RS232_RTS: U8.F2(IO,_DIFFIO_L12p,_(DM2L)/(DM1L0/BWS#1L0)/(DM1L0/BWS#1L0)) ; port RS232.RTS
RS232_RX: U8.H3(IO,_DIFFIO_L5n) ; port RS232.RXD
RS232_TX: U8.D3(IO,_DIFFIO_L1p) ; port RS232.TXD
SCL: R277.2 U8.AD2(IO,_DIFFIO_L46p,_(DQ3L)/(DQ3L)/(DQ1L)) ; port I2C.SCL
SDA: R278.1 U8.V7(IO,_DIFFIO_L45p) ; port I2C.SDA
SDCLK: U8.AE13(IO,_DIFFIO_B25p,_(DQ5B)/(DQ3B)/(DQ5B)) ; port DBSD.CLK
SDCMD: U8.Y14(IO) ; port DBSD.CMD
SDDAT0: U8.AD24(IO,_DIFFIO_R53p)
SDDAT1: U8.AF25(IO,_DIFFIO_B42p,_(DM0B)/(DQ5B)/(DQ5B))
SDDAT2: U8.W16(IO,_DIFFIO_B31n)
SDDAT3: U8.Y12(IO,_DIFFIO_B6n)
SDDETECT: U8.AD14(IO,_DIFFIO_B26n) ; port DBSD.DETECT
SDPROTECT: U8.AC14(IO,_DIFFIO_B25n) ; port DBSD.PROTECT
SPAREIO1: U8.AA10(IO,_DIFFIO_B14n,_(DQ3B)/(DQ3B)/(DQ5B)) ; port SPAREIO.1
SPAREIO2: U8.AA12(IO,_VREFB3N2) ; port SPAREIO.2
SPAREIO3: U8.AB11(IO,_VREFB3N1) ; port SPAREIO.3
SPAREIO4: U8.AB13(IO,_DIFFIO_B10n) ; port SPAREIO.4
SPDIF_IN: U8.AF4(IO,_DIFFIO_B3p,_(DQ1B)/_/_) ; port SPDIF.IN
SPDIF_OUT: U8.AH6(IO,_DIFFIO_B11p,_(DQ1B)/_/_) ; port SPDIF.OUT
SRAM1_A0: U8.G13(IO,_DIFFIO_T18n,_(PADD19))
SRAM1_A1: U8.F15(IO,_DIFFIO_T32p)
SRAM1_A2: U8.D17(IO,_DIFFIO_T37p,_(PADD4),_(DQS2T/CQ3T,DPCLK8)/(DQS2T/CQ3T,DPCLK8)/(DQS2T/CQ3T,DPCLK8))
SRAM1_A3: U8.G19(IO,_DIFFIO_T49n)
SRAM1_A4: U8.A21(IO,_DIFFIO_T43p,_(DQ2T)/(DQ5T)/(DQ5T))
SRAM1_A5: U8.K25(IO,_DIFFIO_R28n)
SRAM1_A6: U8.L25(IO,_DIFFIO_R26p)
SRAM1_A7: U8.H7(IO,_VREFB1N0)
SRAM1_A8: U8.M26(IO,_DIFFIO_R21p,_(DQ0R)/(DQ1R)/(DQ1R))
SRAM1_A9: U8.V1(IO,_(DQ1L)/(DQ3L)/(DQ1L))
SRAM1_A10: U8.R22(IO,_DIFFIO_R38p)
SRAM1_A11: U8.L20(IO,_DIFFIO_R21n)
SRAM1_A12: U8.H22(IO,_DIFFIO_R11n)
SRAM1_A13: U8.J25(IO,_DIFFIO_R13p,__/(DQ1R)/(DQ1R))
SRAM1_A14: U8.J22(IO,_VREFB6N0)
SRAM1_A15: U8.C16(IO,_DIFFIO_T31n,_(PADD9),_(DQ4T)/(DQ5T)/(DQ5T))
SRAM1_A16: U8.H14(IO,_DIFFIO_T30n)
SRAM1_A17: U8.E12(IO,_DIFFIO_T16n,_(DATA14),_(DQS3T/CQ3T#,DPCLK11)/(DQS3T/CQ3T#,DPCLK11)/(DQS3T/CQ3T#,DPCLK11))
SRAM1_A18: U8.G27(IO,_DIFFIO_R12p,_(nOE),_(DQ2R)/(DQ1R)/(DQ1R))
SRAM1_D0: U8.D20(IO,_DIFFIO_T39n,_(DQ4T)/(DQ5T)/(DQ5T))
SRAM1_D1: U8.E22(IO,_DIFFIO_T51n,_(DQ0T)/_/_)
SRAM1_D2: U8.C23(IO,_PLL2_CLKOUTn)
SRAM1_D3: U8.F17(IO,_DIFFIO_T37n)
SRAM1_D4: U8.C26(IO,_DIFFIO_R1p)
SRAM1_D5: U8.G22(IO,_DIFFIO_R7p)
SRAM1_D6: U8.G24(IO,_DIFFIO_R25p)
SRAM1_D7: U8.H23(IO,_DIFFIO_R13n)
SRAM1_D8: U8.G25(IO,_DIFFIO_R10n)
SRAM1_D9: U8.E28(IO,_DIFFIO_R7n,_(PADD23),_(DQ2R)/(DQ1R)/(DQ1R))
SRAM1_D10: U8.D26(IO,_DIFFIO_R1n)
SRAM1_D11: U8.D28(IO,_DIFFIO_R5n,_(PADD22))
SRAM1_D12: U8.G10(IO,_DIFFIO_T12p)
SRAM1_D13: U8.B19(IO,_DIFFIO_T36p,_(PADD6),_(DQ4T)/(DQ5T)/(DQ5T))
SRAM1_D14: U8.D21(IO,_DIFFIO_T45n,_(DQ2T)/(DQ5T)/(DQ5T))
SRAM1_D15: U8.D19(IO,_DIFFIO_T44p)
SRAM1_NBHE: U8.G16(IO,_DIFFIO_T32n) ; port SRAM1.NBHE
SRAM1_NBLE: U8.D18(IO,_DIFFIO_T41p,_(PADD2)) ; port SRAM1.NBLE
SRAM1_NCS: U8.G20(IO,_DIFFIO_T50p) ; port SRAM1.NCS
SRAM1_NOE: U8.E15(IO,_DIFFIO_T28n,_(DM4T)/(DM5T1/BWS#5T1)/(DM5T1/BWS#5T1)) ; port SRAM1.NOE
SRAM1_NWE: U8.K22(IO,_DIFFIO_R20n) ; port SRAM1.NWE
SRAM2_A0: U8.E17(IO,_DIFFIO_T34n,_(DQ4T)/(DQ5T)/(DQ5T))
SRAM2_A1: U8.F18(IO,_VREFB7N1)
SRAM2_A2: U8.B21(IO,_DIFFIO_T42n,_(DQ2T)/(DQ5T)/(DQ5T))
SRAM2_A3: U8.E19(IO,_RDN4)
SRAM2_A4: U8.F19(IO,_RUP4)
SRAM2_A5: U8.J23(IO,_DIFFIO_R18n)
SRAM2_A6: U8.M25(IO,_VREFB6N2)
SRAM2_A7: U8.R21(IO,_DIFFIO_R29p)
SRAM2_A8: U8.L27(IO,_DIFFIO_R17n,_(DQ0R)/(DQ1R)/(DQ1R))
SRAM2_A9: U8.U20(IO,_DIFFIO_R42n)
SRAM2_A10: U8.M28(IO,_DIFFIO_R22n,_(DQ0R)/(DQ1R)/(DQ1R))
SRAM2_A11: U8.N25(IO,_DIFFIO_R25n)
SRAM2_A12: U8.M24(IO,_DIFFIO_R28p)
SRAM2_A13: U8.N21(IO,_VREFB6N3)
SRAM2_A14: U8.L23(IO,_DIFFIO_R20p)
SRAM2_A15: U8.E18(IO,_DIFFIO_T42p,_(DQ2T)/(DQ5T)/(DQ5T))
SRAM2_A16: U8.H16(IO,_DIFFIO_T33p)
SRAM2_A17: U8.D16(IO,_DIFFIO_T31p,_(PADD10))
SRAM2_A18: U8.L22(IO,_DIFFIO_R23p)
SRAM2_D0: U8.J17(IO,_DIFFIO_T33n)
SRAM2_D1: U8.G21(IO)
SRAM2_D2: U8.C25(IO,_DIFFIO_T48p,_(DQ0T)/_/_)
SRAM2_D3: U8.H19(IO,_DIFFIO_T47n)
SRAM2_D4: U8.J19(IO,_DIFFIO_T51p)
SRAM2_D5: U8.E26(IO,_DIFFIO_R3n)
SRAM2_D6: U8.E27(IO,_DIFFIO_R6n,_(DQ2R)/(DQ1R)/(DQ1R))
SRAM2_D7: U8.E1(IO,_DIFFIO_L11p,__/(DQ1L)/(DQ1L))
SRAM2_D8: U8.F27(IO,_DIFFIO_R8p,_(RDY))
SRAM2_D9: U8.F26(IO,_(DQ2R)/(DQ1R)/(DQ1R))
SRAM2_D10: U8.D27(IO,_DIFFIO_R5p,_(PADD21),_(DQ2R)/(DQ1R)/(DQ1R))
SRAM2_D11: U8.E25(IO,_DIFFIO_R16n)
SRAM2_D12: U8.A19(IO,_DIFFIO_T36n,_(PADD5),_(DQ4T)/(DQ5T)/(DQ5T))
SRAM2_D13: U8.B25(IO,_(DQ0T)/_/_)
SRAM2_D14: U8.A26(IO,_DIFFIO_T50n,_(DQ0T)/_/_)
SRAM2_D15: U8.E21(IO,_DIFFIO_T46p)
SRAM2_NBHE: U8.C21(IO,_DIFFIO_T44n,_(DQ2T)/(DQ5T)/(DQ5T)) ; port SRAM2.NBHE
SRAM2_NBLE: U8.B23(IO,_DIFFIO_T47p,_(DM0T)/_/_) ; port SRAM2.NBLE
SRAM2_NCS: U8.J10(IO,_DIFFIO_T10p) ; port SRAM2.NCS
SRAM2_NOE: U8.C20(IO,_DIFFIO_T40n,_(DM2T)/(DM5T0/BWS#5T0)/(DM5T0/BWS#5T0)) ; port SRAM2.NOE
SRAM2_NWE: U8.M21(IO,_VREFB6N1) ; port SRAM2.NWE
SW0: U8.M3(IO,_DIFFIO_L21p)
SW1: U8.W1(IO,_DIFFIO_L35n,_(DM1L/BWS#1L)/(DM3L0/BWS#3L0)/(DM1L2/BWS#1L2))
SW2: U8.AB1(IO,_DIFFIO_L34n)
SW3: U8.AB6(IO,_DIFFIO_L51p)
SW4: U8.AA3(IO)
TCK: R9#1.2 ; sheet U_FPGA_Power/TCK
TDI: R12#1.2 ; sheet U_FPGA_Power/TDI
TDO: R10#1.2 ; sheet U_FPGA_Power/TDO
TFT_BLIGHT: U8.AF26(IO,_DIFFIO_B48n,_(DQS0B/CQ1B,CDPCLK3)/(DQS0B/CQ1B,CDPCLK3)/(DQS0B/CQ1B,CDPCLK3)) ; port TFT_IO.BL
TFT_CS: U8.AG18(IO,_DIFFIO_B34n,_(DQ4B)/(DQ5B)/(DQ5B)) ; port TFT_IO.CS
TFT_DB0: U8.AF15(IO,_DIFFIO_B30p,_(DQ4B)/(DQ5B)/(DQ5B))
TFT_DB1: U8.AD17(IO,_DIFFIO_B36p,_(DQ2B)/(DQ5B)/(DQ5B))
TFT_DB2: U8.AH12(IO,_DIFFIO_B18n)
TFT_DB3: U8.AG17(IO,_DIFFIO_B30n,_(DQ4B)/(DQ5B)/(DQ5B))
TFT_DB4: U8.AG26(IO,_DIFFIO_B51n,_(DQ0B)/_/_)
TFT_DB5: U8.AH18(IO,_DIFFIO_B35p,_(DQ4B)/(DQ5B)/(DQ5B))
TFT_DB6: U8.AH17(IO,_DIFFIO_B31p,_(DQ4B)/(DQ5B)/(DQ5B))
TFT_DB7: U8.AE12(IO,_DIFFIO_B22n,_(DQ5B)/(DQ3B)/(DQ5B))
TFT_DB10: U8.AE23(IO,_PLL4_CLKOUTp)
TFT_DB11: U8.AH26(IO)
TFT_DB12: U8.AE20(IO,_DIFFIO_B45n)
TFT_DB13: U8.AA17(IO,_RUP2)
TFT_DB14: U8.AF21(IO,_DIFFIO_B47p)
TFT_DB15: U8.AB18(IO,_DIFFIO_B44p)
TFT_DB16: U8.AF18(IO,_DIFFIO_B36n)
TFT_DB17: U8.AB17(IO,_RDN2)
TFT_RD: U8.AF22(IO,_DIFFIO_B50n,_(DQ0B)/_/_) ; port TFT_IO.RD
TFT_RESET: U8.Y17(IO,_VREFB4N2) ; port TFT_IO.RESET
TFT_RS: U8.AF20(IO,_DIFFIO_B42n,_(DQ0B)/_/_) ; port TFT_IO.RS
TFT_TSC_BUSY: U8.W28(IO,_DIFFIO_R41p,_(DQ1R)/(DQ3R)/(DQ1R)) ; port TFT_TSC.BUSY
TFT_TSC_CLK: U8.AB16(IO,_DIFFIO_B33p,_(DQ4B)/(DQ5B)/(DQ5B)) ; port TFT_TSC.CLK
TFT_TSC_CS_N: U8.AD28(IO,_DIFFIO_R50n,_(DQ3R)/(DQ3R)/(DQ1R)) ; port TFT_TSC.CS_N
TFT_TSC_DIN: U8.AD25(IO) ; port TFT_TSC.DIN
TFT_TSC_DOUT: U8.AA22(IO,_RUP3) ; port TFT_TSC.DOUT
TFT_TSC_IRQ_N: U8.AB19(IO,_DIFFIO_B46n) ; port TFT_TSC.TFT_INT
TFT_WR: U8.AF23(IO,_PLL4_CLKOUTn) ; port TFT_IO.WR
TMS: R8#1.2 ; sheet U_FPGA_Power/TMS
USB_D0: U8.AF19(IO,_DIFFIO_B41n)
USB_D1: U8.Y19(IO,_DIFFIO_B43p)
USB_D2: U8.AG19(IO,_DIFFIO_B39n)
USB_D3: U8.AA16(IO)
USB_D4: U8.AE28(IO,_DIFFIO_R51n,_(DQ3R)/(DQ3R)/(DQ1R))
USB_D5: U8.AH21(IO,_DIFFIO_B38p,_(DQ2B)/(DQ5B)/(DQ5B))
USB_D6: U8.AG21(IO,_DIFFIO_B37p,_(DQ2B)/(DQ5B)/(DQ5B))
USB_D7: U8.AH22(IO,_DIFFIO_B39p,_(DQ2B)/(DQ5B)/(DQ5B))
USB_FIFOADR0: U8.AC18(IO,_VREFB4N1) ; port DBUSB.FIFOADR0
USB_FIFOADR1: U8.AC25(IO,_DIFFIO_R52n) ; port DBUSB.FIFOADR1
USB_FIFOADR2: U8.AC19(IO,_DIFFIO_B46p) ; port DBUSB.FIFOADR2
USB_FLAGA: U8.AE18(IO,_(DQS2B/CQ3B,DPCLK5)/(DQS2B/CQ3B,DPCLK5)/(DQS2B/CQ3B,DPCLK5)) ; port DBUSB.FLAGA
USB_FLAGB: U8.AD18(IO,_(DQ0B)/_/_) ; port DBUSB.FLAGB
USB_FLAGC: U8.AD22(IO,_DIFFIO_B52p) ; port DBUSB.FLAGC
USB_FLAGD_CS_N: U8.AG22(IO,_DIFFIO_B38n,_(DQ2B)/(DQ5B)/(DQ5B)) ; port DBUSB.FLAGD_CS_N
USB_IFCLK: U8.AE15(IO,_DIFFIO_B29n,__/(DQ5B)/(DQ5B)) ; port DBUSB.IFCLK
USB_INT_N: U8.AF24(IO,_DIFFIO_B41p,_(DQ2B)/(DQ5B)/(DQ5B)) ; port DBUSB.INT_N
USB_PKTEND: U8.AH23(IO,_DIFFIO_B40p,_(DQ2B)/(DQ5B)/(DQ5B)) ; port DBUSB.PKTEND
USB_RD_N: U8.AB22(IO,_DIFFIO_R56p) ; port DBUSB.RD_N
USB_READY: U8.R27(IO,__/(DQ1R)/(DQ1R)) ; port DBUSB.READY
USB_RESET_N: U8.AG25(IO,_DIFFIO_B49p) ; port DBUSB.RESET_N
USB_SLOE: U8.AD19(IO,_DIFFIO_B45p) ; port DBUSB.SLOE
USB_VBUS: U8.AE19(IO,_DIFFIO_B40n,_(DQ2B)/(DQ5B)/(DQ5B)) ; port DBUSB.VBUS
USB_WR_N: U8.W20(IO,_DIFFIO_R34n) ; port DBUSB.WR_N
VGA_BLUE0: U8.H12(IO,_DIFFIO_T21n)
VGA_BLUE1: U8.F11(IO,_VREFB8N1)
VGA_BLUE2: U8.J12(IO,_DIFFIO_T21p)
VGA_BLUE3: U8.G12(IO,_VREFB8N2)
VGA_BLUE4: U8.B11(IO,_DIFFIO_T20p,_(DATA3),_(DQ5T)/(DQ3T)/(DQ5T))
VGA_BLUE5: U8.D10(IO,_DIFFIO_T15n,_(DQ3T)/(DQ3T)/(DQ5T))
VGA_BLUE6: U8.G11(IO,_DIFFIO_T11n)
VGA_BLUE7: U8.E10(IO,_DIFFIO_T13n)
VGA_CLK: U8.B6(IO,_DIFFIO_T8p,_(DATA6),_(DQ3T)/(DQ3T)/(DQ5T)) ; port VGA.VGA_CLK
VGA_GREEN0: U8.D9(IO,_DIFFIO_T6p,_(DATA8))
VGA_GREEN1: U8.A8(IO,_DIFFIO_T5n,_(DATA9),_(DM3T/BWS#3T)/(DM3T1/BWS#3T1)/(DM5T3/BWS#5T3))
VGA_GREEN2: U8.D8(IO,_(DQ1T)/_/_)
VGA_GREEN3: U8.C8(IO,_DIFFIO_T5p,_(DQ1T)/_/_)
VGA_GREEN4: U8.D7(IO,_DIFFIO_T4p,_(DATA11))
VGA_GREEN5: U8.E7(IO,_DIFFIO_T13p)
VGA_GREEN6: U8.F7(IO,_DIFFIO_T9p)
VGA_GREEN7: U8.E5(IO,_DIFFIO_L3p)
VGA_HSYNC: U8.C12(IO,_DIFFIO_T24n,_(PADD16),_(DQ5T)/(DQ3T)/(DQ5T)) ; port VGA.VGA_HSYNC
VGA_RED0: U8.A10(IO,_DIFFIO_T19n,_(PADD18))
VGA_RED1: U8.B10(IO,_DIFFIO_T19p,_(DATA4),_(DM5T/BWS#5T)/(DM3T0/BWS#3T0)/(DM5T2/BWS#5T2))
VGA_RED2: U8.F10(IO,_DIFFIO_T15p)
VGA_RED3: U8.H10(IO,_DIFFIO_T7p)
VGA_RED4: U8.C10(IO,_DIFFIO_T17p,_(DQ3T)/(DQ3T)/(DQ5T))
VGA_RED5: U8.G8(IO)
VGA_RED6: U8.G9(IO,_VREFB8N3)
VGA_RED7: U8.C9(IO,_DIFFIO_T6n,_(DQ3T)/(DQ3T)/(DQ5T))
VGA_VSYNC: U8.H13(IO,_DIFFIO_T18p,_(DATA15),_(DQ3T)/(DQ3T)/(DQ5T)) ; port VGA.VGA_VSYNC
NetR14#1_1: R14#1.1 U8.N7(IO,_(DATA0))
NetR213_2: R213.2 U70.7(CLK4)
NetR314_2: R314.2 U70.2(CLK2)

Not connected (* = marked no-connect by the designer): U8 A3(IO,_DIFFIO_T2n,_(DQ1T)/_/_)* A4(IO,_DIFFIO_T3n,_(DQ1T)/_/_)* A7(IO,_DIFFIO_T12n,_(DQ3T)/(DQ3T)/(DQ5T))* A11(IO,_DIFFIO_T20n,_(DATA2),_(DQ5T)/(DQ3T)/(DQ5T))* A18(IO,_DIFFIO_T35n,_(PADD7))* A22(IO,_DIFFIO_T43n,_(DQ2T)/(DQ5T)/(DQ5T))* A23(IO,_(DQ0T)/_/_)* AA4(IO,_DIFFIO_L47n,_(DQ3L)/(DQ3L)/(DQ1L))* AA14(IO,_VREFB3N0)* AA19(IO,_DIFFIO_B44n)* AB9(IO,_DIFFIO_B12p,_(DM3B/BWS#3B)/(DM3B1/BWS#3B1)/(DM5B3/BWS#5B3))* AB21(IO,_DIFFIO_B53p)* AC4(IO,_DIFFIO_L52p)* AC5(IO,_DIFFIO_L53p)* AC15(IO,_DIFFIO_B28n,_(DM4B)/(DM5B1/BWS#5B1)/(DM5B1/BWS#5B1))* AC17(IO,_DIFFIO_B37n)* AD4(IO)* AD15(IO,_DIFFIO_B29p)* AE11(IO,_DIFFIO_B23p,_(DQ5B)/(DQ3B)/(DQ5B))* AE16(IO,_DIFFIO_B33n)* AE17(IO,_DIFFIO_B34p,_(DQ4B)/(DQ5B)/(DQ5B))* AE21(IO,_DIFFIO_B43n,_(DQ0B)/_/_)* AE24(IO,_DIFFIO_B51p,_(DQ0B)/_/_)* B17(IO,_DIFFIO_T29p,_(PADD12),_(DQS4T/CQ5T,DPCLK9)/(DQS4T/CQ5T,DPCLK9)/(DQS4T/CQ5T,DPCLK9))* B22(IO,_DIFFIO_T45p,_(PADD0))* B26(IO,_DIFFIO_T52n,_(DQ0T)/_/_)* C5(IO,_PLL3_CLKOUTn)* C22(IO,_(DQ2T)/(DQ5T)/(DQ5T))* C24(IO,_DIFFIO_T46n,_(DQ2T)/(DQ5T)/(DQ5T))* D4(IO,_(DM1T)/_/_)* D5(IO,_PLL3_CLKOUTp)* D11(IO)* D12(IO,_DIFFIO_T24p,_(PADD17),_(DQS5T/CQ5T#,DPCLK10)/(DQS5T/CQ5T#,DPCLK10)/(DQS5T/CQ5T#,DPCLK10))* D14(IO,_DIFFIO_T25p,_(PADD15))* D22(IO,_DIFFIO_T52p,_(DQ0T)/_/_)* D23(IO,_PLL2_CLKOUTp)* D24(IO,_DIFFIO_R2p)* E11(IO,_DIFFIO_T14n,_(DQ3T)/(DQ3T)/(DQ5T))* E14(IO,_(DQ5T)/(DQ3T)/(DQ5T))* E24(IO,_DIFFIO_R3p)* F12(IO,_DIFFIO_T16p,_(DATA13))* F21(IO,_DIFFIO_T48n,_(DQ0T)/_/_)* F22(IO,_VREFB7N0)* F24(IO,_DIFFIO_R15n)* F25(IO,_DIFFIO_R4p)* G17(IO,_VREFB7N2)* G18(IO,_DIFFIO_T38p)* G23(IO,_DIFFIO_R9p)* G28(IO,_DIFFIO_R12n,_(nWE),_(DQ2R)/(DQ1R)/(DQ1R))* H15(IO)* H17(IO,_DIFFIO_T40p)* H21(IO,_DIFFIO_R6p)* H24(IO,_DIFFIO_R11p)* J14(IO,_DIFFIO_T28p)* J16(IO,_DIFFIO_T34p)* J24(IO,_DIFFIO_R14n)* K15(IO,_DIFFIO_T30p)* L24(IO,_DIFFIO_R17p,_(DQ0R)/(DQ1R)/(DQ1R))* N8(IO,_VREFB1N2)* T4(IO,_DIFFIO_L30p,_(DQ1L)/(DQ3L)/(DQ1L))* T7(IO,_VREFB2N1)* T25(IO,_DIFFIO_R33p,_(DQS1R/CQ1R#,DPCLK6)/(DQS1R/CQ1R#,DPCLK6)/(DQS1R/CQ1R#,DPCLK6))* U23(IO,_VREFB5N1)* U24(IO,_VREFB5N2)* V20(IO,_DIFFIO_R33n)* V23(IO,_DIFFIO_R36n)* W25(IO)* Y5(IO,_DIFFIO_L38p)* Y6(IO,_DIFFIO_L38n)* Y15(IO,_DIFFIO_B15n)* Y24(IO,_DIFFIO_R48n,_(DQ3R)/(DQ3R)/(DQ1R))* Y25(IO,_DIFFIO_R35n)*; U70 3(CLK1)* 5(CLK3)* 8(CLKOUT)*

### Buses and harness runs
bus BUS_A[17..1]
bus BUS_A[24..1]
bus BUS_D[31..0]
bus BUS_NBE[3..0]
bus DIP[7..0]
bus E_RXD[3..0]
bus E_TXD[3..0]
bus EXTEND_A[49..0]
bus FPGA_ID[3..0]
bus FPGA_M[2..0]
bus IO[35..0]
bus RELAY[3..0]
bus SDDAT[3..0]
bus SRAM1_A[18..0]
bus SRAM1_D[15..0]
bus SRAM2_A[18..0]
bus SRAM2_D[15..0]
bus SW[4..0]
bus TFT_DB[17..0]
bus USB_D[15..0]
bus VGA_BLUE[7..0]
bus VGA_GREEN[7..0]
bus VGA_RED[7..0]

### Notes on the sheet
- USER/DB FPGA
- JTAG
- PROGRAM
- SPI
- CLOCKS
- COMMON MEMORY RESOURCES
- (near NT3#2) STANDALON MEMORY RESOURCES
- AVOID PIN
- PERIPHERALS
- USB2
- PLL1
- PLL2
- PLL3
- PLL4
- (near R4#2) 1V2
- 3V3
- (near NT2#2) FPGA_ID = 0x1 (Altera)

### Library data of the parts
NT2#2 NT3#2 NT3#3 NT4 NT5 = D-002-0002: Net-Tie, Surface Mount, 2 x 0.4mm x 0.2mm SMT Pads - For 0.2mm Track
R1#2 R2#2 R3#2 R4#2 R277 R278 R283 = D-100-0088: as R98 on sheet Audio_Codec
R8#1 R9#1 R10#1 R12#1 R14#1 R18#1 R20#1 R22#1 R23#1 R24#1 = D-100-0131: Resistor, 100R 1% 0402 (1005); Power Rating: 63 mW
R213 R314 = D-100-0085: Resistor, 5R6 1% 0402 (1005); Power Rating: 63 mW; Resistance: 5.6 R
R272-R275 = D-100-0107: Resistor, 2K2 1% 0402 (1005); Power Rating: 63 mW; Resistance: 2.2 K
U8 = D-241-0023: FPGA, Altera Cyclone3-40 F780; Supply Voltage: mV
U70 = D-200-0000: CY2305 Zero-Delay Buffer SOIC 8-pin 150mil body; Supply Voltage: 3.3 V

## Sheet FPGA_Bypass_1V2.SCHDOC: FPGA Bypass 1V2
size A4; Organization: Altium Limited.; Address1: Level 3, 12a Rodborough Rd; Address2: Frenchs Forest 2086; Address3: NSW; Address4: AUSTRALIA; DocumentNumber: 60; SheetNumber: 61; SheetTotal: 78; PageSetup: Record=PageOptions|CenterHorizontal=True|CenterVertical=True|PrintScale=0.97|XCorrection=1.00|YCorrection=1.00|PrintKind=0|BorderSize=5000000|LeftOffset=0|BottomOffset=0|Orientation=2|PaperLength=1000|PaperWidth=1000|Scale=100|PaperSource=7|PrintQuality=-4|MediaType=1|DitherType=10|PaperKind=A4 (210 x 297 mm)|PrintScaleMode=1
Used 2 times, as channels USER_DECOUPLING_CAPS_1V2, HOST_DECOUPLING_CAPS_1V2. Parts and nets are listed once, with the designators drawn on the sheet.
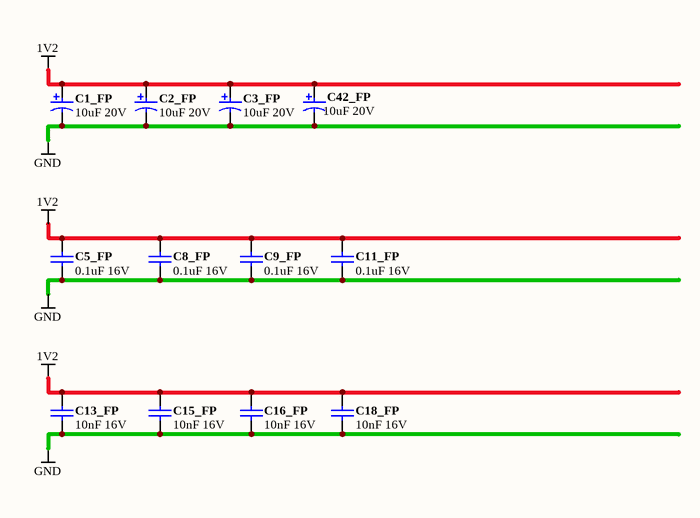
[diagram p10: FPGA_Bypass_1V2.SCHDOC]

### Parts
C1_FP  10uF 20V  [CAPC3528-STAR]
C2_FP  10uF 20V  [CAPC3528-STAR]
C3_FP  10uF 20V  [CAPC3528-STAR]
C5_FP  0.1uF 16V  [CAPC1005-STAR]
C8_FP  0.1uF 16V  [CAPC1005-STAR]
C9_FP  0.1uF 16V  [CAPC1005-STAR]
C11_FP  0.1uF 16V  [CAPC1005-STAR]
C13_FP  10nF 16V  [CAPC1005-STAR]
C15_FP  10nF 16V  [CAPC1005-STAR]
C16_FP  10nF 16V  [CAPC1005-STAR]
C18_FP  10nF 16V  [CAPC1005-STAR]
C42_FP  10uF 20V  [CAPC3528-STAR]

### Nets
1V2: C1_FP.1 C2_FP.1 C3_FP.1 C5_FP.1 C8_FP.1 C9_FP.1 C11_FP.1 C13_FP.1 C15_FP.1 C16_FP.1 C18_FP.1 C42_FP.1
GND: C1_FP.2 C2_FP.2 C3_FP.2 C5_FP.2 C8_FP.2 C9_FP.2 C11_FP.2 C13_FP.2 C15_FP.2 C16_FP.2 C18_FP.2 C42_FP.2

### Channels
USER_DECOUPLING_CAPS_1V2: designators end in A
HOST_DECOUPLING_CAPS_1V2: designators end in B

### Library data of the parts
C1_FP C2_FP C3_FP C42_FP = D-101-0007: as C3#2 on sheet PSU
C5_FP C8_FP C9_FP C11_FP = D-101-0080: as C1#1 on sheet VIDEO_DAC_THS8134B
C13_FP C15_FP C16_FP C18_FP = D-101-0077: Capacitor, Ceramic, 10nF 10% 16V 0402 (1005) X7R; Polarity: Non-Polarized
